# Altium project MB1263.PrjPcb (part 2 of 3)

## Sheet MPU_18x18.SchDoc: MPU_18x18
size A3; DocumentNumber: MB1263; Revision: C-04; SheetNumber: 3; SheetTotal: 11; Project: STM32MP157-EVAL
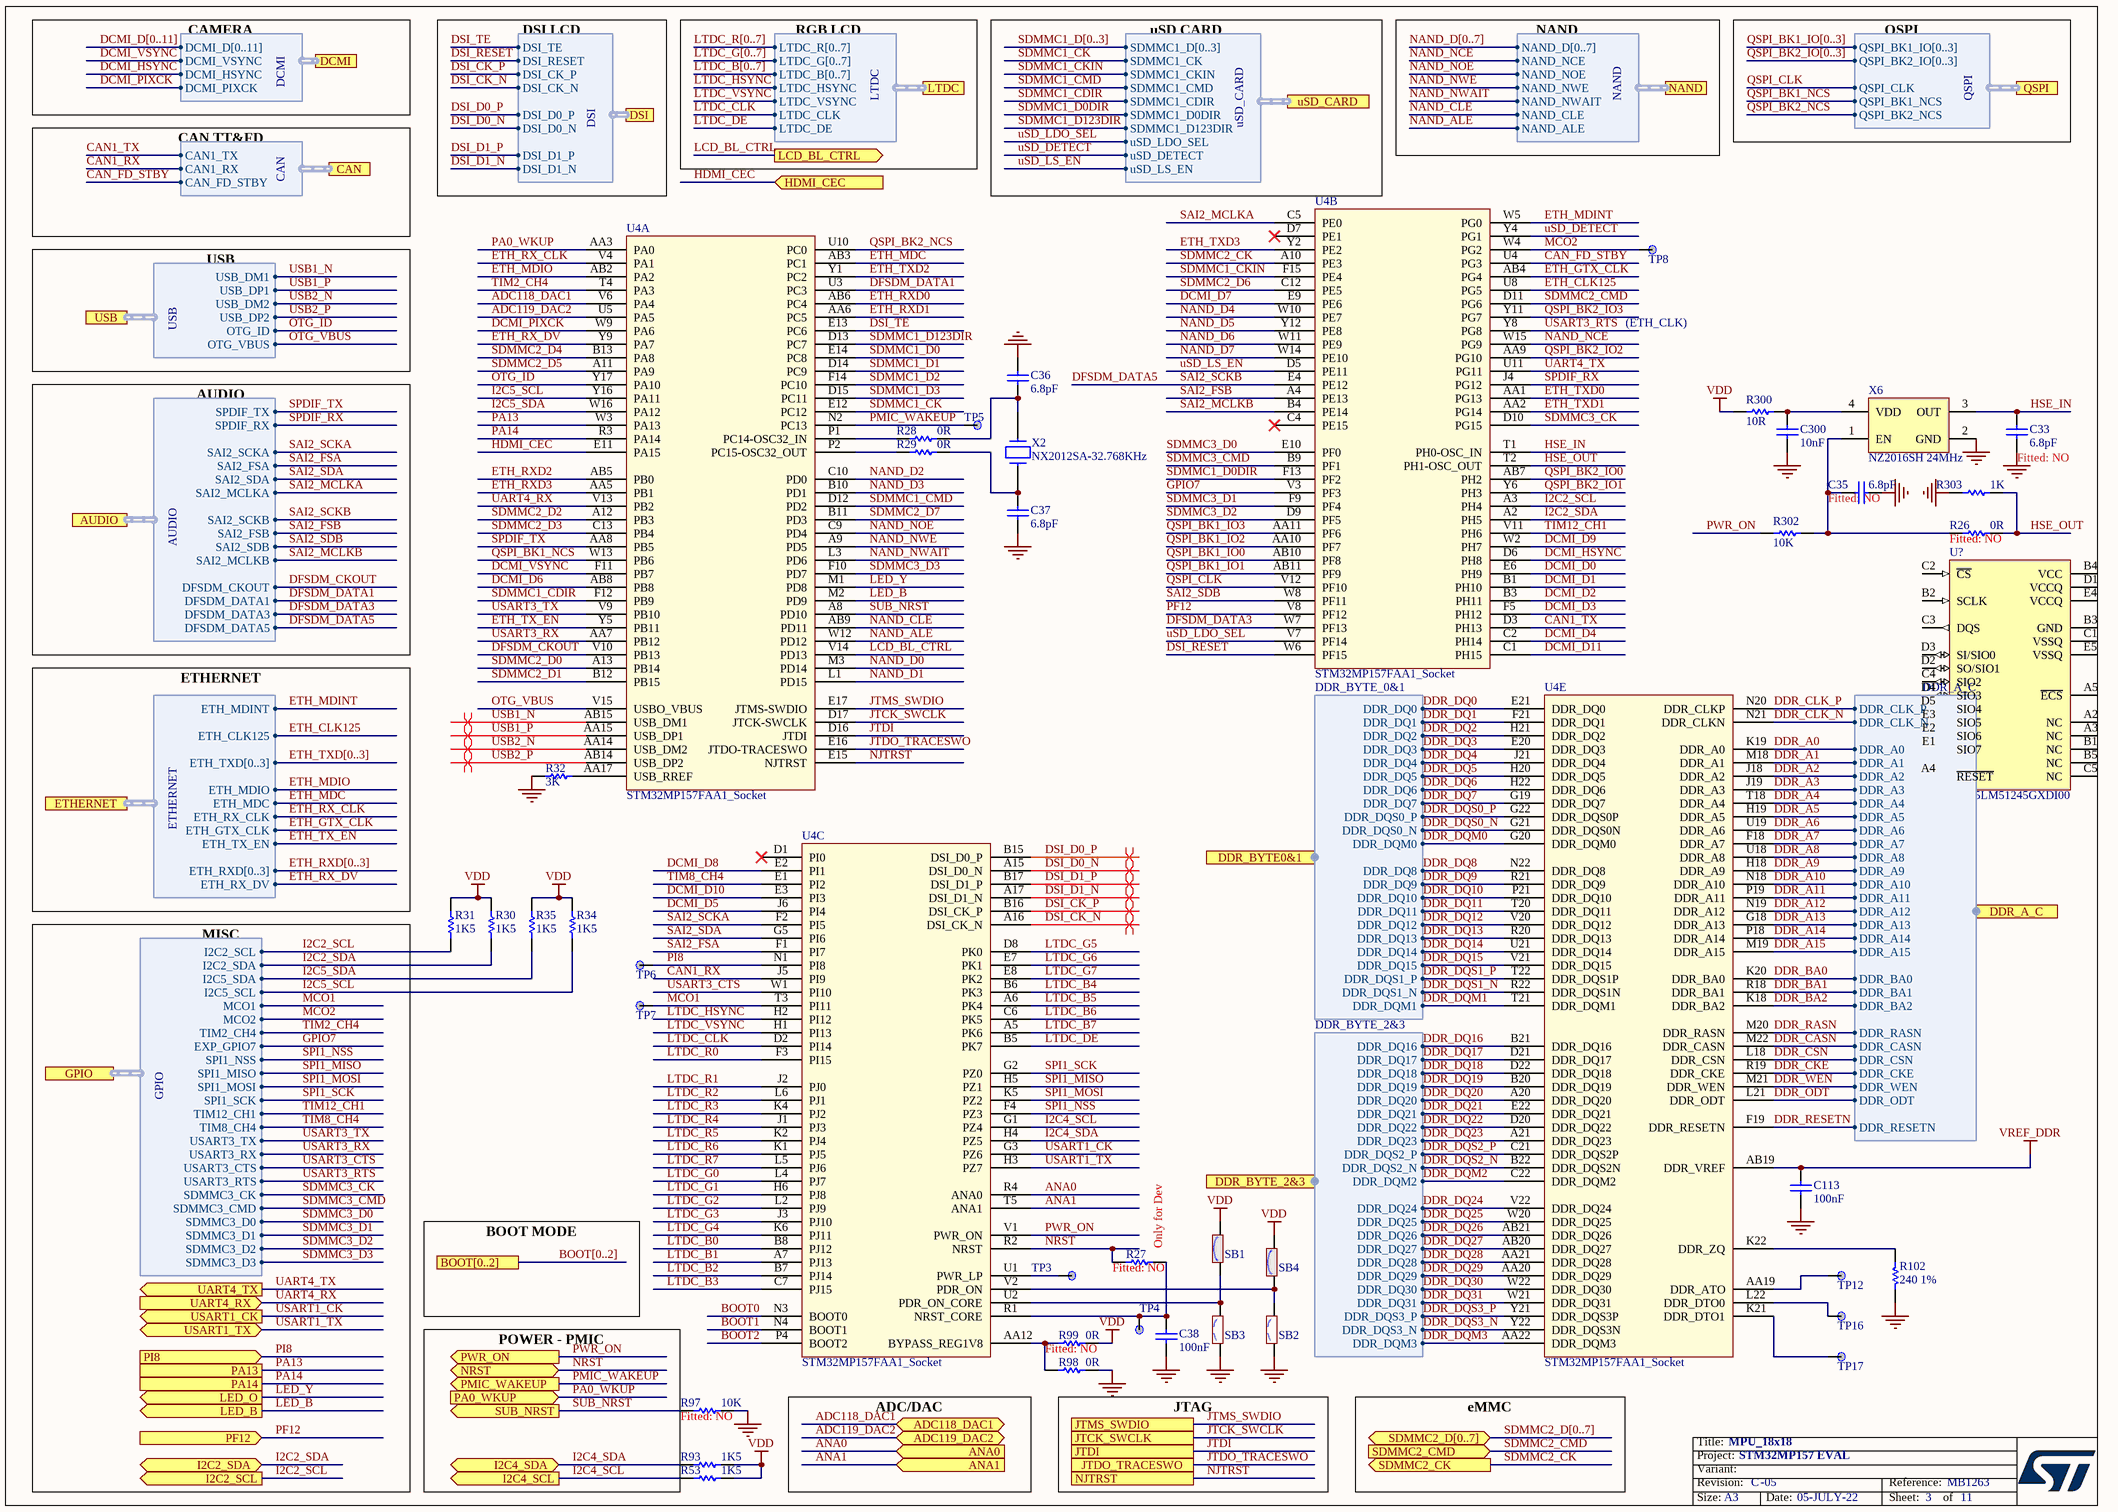
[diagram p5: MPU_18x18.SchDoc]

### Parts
C33  Fitted: NO  [C0402]  (hidden comment: 6.8pF)
C35  Fitted: NO  [C0402]  (hidden comment: 6.8pF)
C36  6.8pF  [C0402]
C37  6.8pF  [C0402]
C38  100nF  [C0402]
C113  100nF  [C0402]
C300  10nF  [C0402]
R26  0R  Fitted: NO  [R0402]
R27  Fitted: NO  [R0402]  (hidden comment: 0R)
R28  0R  [R0402]
R29  0R  [R0402]
R30  1K5  [R0402]
R31  1K5  [R0402]
R32  3K  [R0402]
R34  1K5  [R0402]
R35  1K5  [R0402]
R53  1K5  [R0402]
R93  1K5  [R0402]
R97  10K  Fitted: NO  [R0402]
R98  0R  [R0402]
R99  0R  Fitted: NO  [R0402]
R102  240 1%  [R0402]
R300  value 10R  [R0402]  (hidden comment: Resistor)
R302  10K  [R0402]
R303  1K  [R0402]
SB1  SB_ON  [SOLDER-BRIDGE_R0603-0R]  (value not drawn)
SB2  SB_OFF  [SOLDER-BRIDGE_R0603-0R]  (value not drawn)
SB3  SB_OFF  [SOLDER-BRIDGE_R0603-0R]  (value not drawn)
SB4  SB_ON  [SOLDER-BRIDGE_R0603-0R]  (value not drawn)
TP3  TP  [TP_SMD_1MM]  (value not drawn)  (no BOM)
TP4  TP  [TP_SMD_1MM]  (value not drawn)  (no BOM)
TP5  TP  [TP_SMD_1MM]  (value not drawn)  (no BOM)
TP6  TP  [TP_SMD_1MM]  (value not drawn)  (no BOM)
TP7  TP  [TP_SMD_1MM]  (value not drawn)  (no BOM)
TP8  TP  [TP_SMD_1MM]  (value not drawn)  (no BOM)
TP12  TP 0.6  [TP_SMD_0-6MM]  (value not drawn)  (no BOM)
TP16  TP 0.6  [TP_SMD_0-6MM]  (value not drawn)  (no BOM)
TP17  TP 0.6  [TP_SMD_0-6MM]  (value not drawn)  (no BOM)
U4  STM32MP157FAA1_Socket  [ICC_LFBGA448_18X18_STM32MP157BAA3_P080__SOCKET_IE_CS1627194MF]  (parts A,B,C,E of 5)
U?  value MX25LM51245GXDI00  [ICC_BGA24_5X5-BALL-ARRAY_6X8_P1]  (hidden comment: MX25xx51245GXDx00)
X2  NX2012SA-32.768KHz  [CRY_NX2012SA_2P]
X6  value NZ2016SH 24MHz  [CRY_NZ2016SH_4P]  (hidden comment: OSCILLATOR_4_PINS)

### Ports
ADC118_DAC1 (bidir), ADC119_DAC2 (bidir), ANA0 (in), ANA1 (in), AUDIO (harness AUDIO), BOOT[0..2], CAN (harness CAN), DCMI (harness DCMI), DDR_A_C (harness DDR_A_C), DDR_BYTE0&1 (harness DDR_BYTE_0&1), DDR_BYTE_2&3 (harness DDR_BYTE_2&3), DSI (harness DSI), ETHERNET (harness ETHERNET), GPIO (harness GPIO), HDMI_CEC (in), I2C2_SCL (out), I2C2_SDA (bidir), I2C4_SCL (out), I2C4_SDA (bidir), JTCK_SWCLK, JTDI, JTDO_TRACESWO, JTMS_SWDIO, LCD_BL_CTRL (out), LED_B (out), LED_O (out), LTDC (harness LTDC), NAND (harness NAND), NJTRST, NRST (bidir), PA0_WKUP (in), PA13, PA14, PF12 (in), PI8 (in), PMIC_WAKEUP (out), PWR_ON (out), QSPI (harness QSPI), SDMMC2_CK (out), SDMMC2_CMD (in), SDMMC2_D[0..7] (bidir), SUB_NRST (out), UART4_RX (in), UART4_TX (out), USART1_CK (out), USART1_TX (bidir), USB (harness USB), uSD_CARD (harness uSD_CARD)

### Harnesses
DDR_BYTE_0&1: DDR_DQ0, DDR_DQ1, DDR_DQ2, DDR_DQ3, DDR_DQ4, DDR_DQ5, DDR_DQ6, DDR_DQ7, DDR_DQS0_P, DDR_DQS0_N, DDR_DQM0, DDR_DQ8, DDR_DQ9, DDR_DQ10, DDR_DQ11, DDR_DQ12, DDR_DQ13, DDR_DQ14, DDR_DQ15, DDR_DQS1_P, DDR_DQS1_N, DDR_DQM1
DDR_BYTE_2&3: DDR_DQ16, DDR_DQ17, DDR_DQ18, DDR_DQ19, DDR_DQ20, DDR_DQ21, DDR_DQ22, DDR_DQ23, DDR_DQS2_P, DDR_DQS2_N, DDR_DQM2, DDR_DQ24, DDR_DQ25, DDR_DQ26, DDR_DQ27, DDR_DQ28, DDR_DQ29, DDR_DQ30, DDR_DQ31, DDR_DQS3_P, DDR_DQS3_N, DDR_DQM3
DDR_A_C: DDR_CLK_P, DDR_CLK_N, DDR_A0, DDR_A1, DDR_A2, DDR_A3, DDR_A4, DDR_A5, DDR_A6, DDR_A7, DDR_A8, DDR_A9, DDR_A10, DDR_A11, DDR_A12, DDR_A13, DDR_A14, DDR_A15, DDR_BA0, DDR_BA1, DDR_BA2, DDR_RASN, DDR_CASN, DDR_CSN, DDR_CKE, DDR_WEN, DDR_ODT, DDR_RESETN
GPIO: I2C2_SCL, I2C2_SDA, I2C5_SDA, MCO1, MCO2, TIM2_CH4, EXP_GPIO7, SPI1_NSS, SPI1_MISO, SPI1_MOSI, SPI1_SCK, TIM12_CH1, TIM8_CH4, USART3_TX, USART3_RX, USART3_CTS, USART3_RTS, SDMMC3_CK, SDMMC3_CMD, SDMMC3_D0, SDMMC3_D1, SDMMC3_D2, SDMMC3_D3, I2C5_SCL
ETHERNET: ETH_MDINT, ETH_CLK125, ETH_TXD[0..3], ETH_MDIO, ETH_MDC, ETH_RX_CLK, ETH_GTX_CLK, ETH_TX_EN, ETH_RXD[0..3], ETH_RX_DV
AUDIO: SPDIF_TX, SPDIF_RX, SAI2_SCKA, SAI2_FSA, SAI2_SDA, SAI2_SDB, SAI2_MCLKA, DFSDM_CKOUT, DFSDM_DATA1, DFSDM_DATA3, DFSDM_DATA5, SAI2_SCKB, SAI2_FSB, SAI2_MCLKB
DCMI: DCMI_D[0..11], DCMI_VSYNC, DCMI_HSYNC, DCMI_PIXCK
DSI: DSI_CK_P, DSI_CK_N, DSI_D0_P, DSI_D0_N, DSI_D1_P, DSI_D1_N, DSI_TE, DSI_RESET
LTDC: LTDC_R[0..7], LTDC_G[0..7], LTDC_B[0..7], LTDC_HSYNC, LTDC_VSYNC, LTDC_CLK, LTDC_DE
NAND: NAND_D[0..7], NAND_NCE, NAND_NOE, NAND_NWE, NAND_NWAIT, NAND_CLE, NAND_ALE
USB: USB_DM1, USB_DP1, USB_DM2, USB_DP2, OTG_ID, OTG_VBUS
QSPI: QSPI_BK1_IO[0..3], QSPI_BK2_IO[0..3], QSPI_CLK, QSPI_BK1_NCS, QSPI_BK2_NCS
uSD_CARD: SDMMC1_D[0..3], SDMMC1_CK, SDMMC1_CKIN, SDMMC1_CMD, SDMMC1_CDIR, SDMMC1_D0DIR, SDMMC1_D123DIR, uSD_LDO_SEL, uSD_DETECT, uSD_LS_EN
CAN: CAN1_TX, CAN1_RX, CAN_FD_STBY

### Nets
GND: C33.1 C35.1 C36.2 C37.1 C38.1 C113.1 C300.1 R32.1 R97.2 R98.2 R102.2 R303.2 SB2.1 SB3.1 X6.2(GND)
VDD: R30.2 R31.2 R34.2 R35.2 R53.1 R93.1 R99.2 R300.1 SB1.2 SB4.2
VREF_DDR: C113.2 U4.AB19(DDR_VREF)
ADC118_DAC1: U4.V6(PA4) ; port ADC118_DAC1
ADC119_DAC2: U4.U5(PA5) ; port ADC119_DAC2
ANA0: U4.R4(ANA0) ; port ANA0
ANA1: U4.T5(ANA1) ; port ANA1
BOOT0: U4.N3(BOOT0)
BOOT1: U4.N4(BOOT1)
BOOT2: U4.P4(BOOT2)
CAN1_RX: U4.J5(PI9) ; port CAN.CAN1_RX
CAN1_TX: U4.D3(PH13) ; port CAN.CAN1_TX
CAN_FD_STBY: U4.U4(PG3) ; port CAN.CAN_FD_STBY
DCMI_D0: U4.E6(PH9)
DCMI_D1: U4.B1(PH10)
DCMI_D2: U4.B3(PH11)
DCMI_D3: U4.F5(PH12)
DCMI_D4: U4.C2(PH14)
DCMI_D5: U4.J6(PI4)
DCMI_D6: U4.AB8(PB8)
DCMI_D7: U4.E9(PE6)
DCMI_D8: U4.E2(PI1)
DCMI_D9: U4.W2(PH7)
DCMI_D10: U4.E3(PI3)
DCMI_D11: U4.C1(PH15)
DCMI_HSYNC: U4.D6(PH8) ; port DCMI.DCMI_HSYNC
DCMI_PIXCK: U4.W9(PA6) ; port DCMI.DCMI_PIXCK
DCMI_VSYNC: U4.F11(PB7) ; port DCMI.DCMI_VSYNC
DDR_A0: U4.K19(DDR_A0) ; port DDR_A_C.DDR_A0
DDR_A1: U4.M18(DDR_A1) ; port DDR_A_C.DDR_A1
DDR_A2: U4.J18(DDR_A2) ; port DDR_A_C.DDR_A2
DDR_A3: U4.J19(DDR_A3) ; port DDR_A_C.DDR_A3
DDR_A4: U4.T18(DDR_A4) ; port DDR_A_C.DDR_A4
DDR_A5: U4.H19(DDR_A5) ; port DDR_A_C.DDR_A5
DDR_A6: U4.U19(DDR_A6) ; port DDR_A_C.DDR_A6
DDR_A7: U4.F18(DDR_A7) ; port DDR_A_C.DDR_A7
DDR_A8: U4.U18(DDR_A8) ; port DDR_A_C.DDR_A8
DDR_A9: U4.H18(DDR_A9) ; port DDR_A_C.DDR_A9
DDR_A10: U4.N18(DDR_A10) ; port DDR_A_C.DDR_A10
DDR_A11: U4.P19(DDR_A11) ; port DDR_A_C.DDR_A11
DDR_A12: U4.N19(DDR_A12) ; port DDR_A_C.DDR_A12
DDR_A13: U4.G18(DDR_A13) ; port DDR_A_C.DDR_A13
DDR_A14: U4.P18(DDR_A14) ; port DDR_A_C.DDR_A14
DDR_A15: U4.M19(DDR_A15) ; port DDR_A_C.DDR_A15
DDR_BA0: U4.K20(DDR_BA0) ; port DDR_A_C.DDR_BA0
DDR_BA1: U4.R18(DDR_BA1) ; port DDR_A_C.DDR_BA1
DDR_BA2: U4.K18(DDR_BA2) ; port DDR_A_C.DDR_BA2
DDR_CASN: U4.M22(DDR_CASN) ; port DDR_A_C.DDR_CASN
DDR_CKE: U4.R19(DDR_CKE) ; port DDR_A_C.DDR_CKE
DDR_CLK_N: U4.N21(DDR_CLKN) ; port DDR_A_C.DDR_CLK_N
DDR_CLK_P: U4.N20(DDR_CLKP) ; port DDR_A_C.DDR_CLK_P
DDR_CSN: U4.L18(DDR_CSN) ; port DDR_A_C.DDR_CSN
DDR_DQ0: U4.E21(DDR_DQ0) ; port DDR_BYTE0&1.DDR_DQ0
DDR_DQ1: U4.F21(DDR_DQ1) ; port DDR_BYTE0&1.DDR_DQ1
DDR_DQ2: U4.H21(DDR_DQ2) ; port DDR_BYTE0&1.DDR_DQ2
DDR_DQ3: U4.E20(DDR_DQ3) ; port DDR_BYTE0&1.DDR_DQ3
DDR_DQ4: U4.J21(DDR_DQ4) ; port DDR_BYTE0&1.DDR_DQ4
DDR_DQ5: U4.H20(DDR_DQ5) ; port DDR_BYTE0&1.DDR_DQ5
DDR_DQ6: U4.H22(DDR_DQ6) ; port DDR_BYTE0&1.DDR_DQ6
DDR_DQ7: U4.G19(DDR_DQ7) ; port DDR_BYTE0&1.DDR_DQ7
DDR_DQ8: U4.N22(DDR_DQ8) ; port DDR_BYTE0&1.DDR_DQ8
DDR_DQ9: U4.R21(DDR_DQ9) ; port DDR_BYTE0&1.DDR_DQ9
DDR_DQ10: U4.P21(DDR_DQ10) ; port DDR_BYTE0&1.DDR_DQ10
DDR_DQ11: U4.T20(DDR_DQ11) ; port DDR_BYTE0&1.DDR_DQ11
DDR_DQ12: U4.V20(DDR_DQ12) ; port DDR_BYTE0&1.DDR_DQ12
DDR_DQ13: U4.R20(DDR_DQ13) ; port DDR_BYTE0&1.DDR_DQ13
DDR_DQ14: U4.U21(DDR_DQ14) ; port DDR_BYTE0&1.DDR_DQ14
DDR_DQ15: U4.V21(DDR_DQ15) ; port DDR_BYTE0&1.DDR_DQ15
DDR_DQ16: U4.B21(DDR_DQ16) ; port DDR_BYTE_2&3.DDR_DQ16
DDR_DQ17: U4.D21(DDR_DQ17) ; port DDR_BYTE_2&3.DDR_DQ17
DDR_DQ18: U4.D22(DDR_DQ18) ; port DDR_BYTE_2&3.DDR_DQ18
DDR_DQ19: U4.B20(DDR_DQ19) ; port DDR_BYTE_2&3.DDR_DQ19
DDR_DQ20: U4.A20(DDR_DQ20) ; port DDR_BYTE_2&3.DDR_DQ20
DDR_DQ21: U4.E22(DDR_DQ21) ; port DDR_BYTE_2&3.DDR_DQ21
DDR_DQ22: U4.D20(DDR_DQ22) ; port DDR_BYTE_2&3.DDR_DQ22
DDR_DQ23: U4.A21(DDR_DQ23) ; port DDR_BYTE_2&3.DDR_DQ23
DDR_DQ24: U4.V22(DDR_DQ24) ; port DDR_BYTE_2&3.DDR_DQ24
DDR_DQ25: U4.W20(DDR_DQ25) ; port DDR_BYTE_2&3.DDR_DQ25
DDR_DQ26: U4.AB21(DDR_DQ26) ; port DDR_BYTE_2&3.DDR_DQ26
DDR_DQ27: U4.AB20(DDR_DQ27) ; port DDR_BYTE_2&3.DDR_DQ27
DDR_DQ28: U4.AA21(DDR_DQ28) ; port DDR_BYTE_2&3.DDR_DQ28
DDR_DQ29: U4.AA20(DDR_DQ29) ; port DDR_BYTE_2&3.DDR_DQ29
DDR_DQ30: U4.W22(DDR_DQ30) ; port DDR_BYTE_2&3.DDR_DQ30
DDR_DQ31: U4.W21(DDR_DQ31) ; port DDR_BYTE_2&3.DDR_DQ31
DDR_DQM0: U4.G20(DDR_DQM0) ; port DDR_BYTE0&1.DDR_DQM0
DDR_DQM1: U4.T21(DDR_DQM1) ; port DDR_BYTE0&1.DDR_DQM1
DDR_DQM2: U4.C22(DDR_DQM2) ; port DDR_BYTE_2&3.DDR_DQM2
DDR_DQM3: U4.AA22(DDR_DQM3) ; port DDR_BYTE_2&3.DDR_DQM3
DDR_DQS0_N: U4.G21(DDR_DQS0N) ; port DDR_BYTE0&1.DDR_DQS0_N
DDR_DQS0_P: U4.G22(DDR_DQS0P) ; port DDR_BYTE0&1.DDR_DQS0_P
DDR_DQS1_N: U4.R22(DDR_DQS1N) ; port DDR_BYTE0&1.DDR_DQS1_N
DDR_DQS1_P: U4.T22(DDR_DQS1P) ; port DDR_BYTE0&1.DDR_DQS1_P
DDR_DQS2_N: U4.B22(DDR_DQS2N) ; port DDR_BYTE_2&3.DDR_DQS2_N
DDR_DQS2_P: U4.C21(DDR_DQS2P) ; port DDR_BYTE_2&3.DDR_DQS2_P
DDR_DQS3_N: U4.Y22(DDR_DQS3N) ; port DDR_BYTE_2&3.DDR_DQS3_N
DDR_DQS3_P: U4.Y21(DDR_DQS3P) ; port DDR_BYTE_2&3.DDR_DQS3_P
DDR_ODT: U4.L21(DDR_ODT) ; port DDR_A_C.DDR_ODT
DDR_RASN: U4.M20(DDR_RASN) ; port DDR_A_C.DDR_RASN
DDR_RESETN: U4.F19(DDR_RESETN) ; port DDR_A_C.DDR_RESETN
DDR_WEN: U4.M21(DDR_WEN) ; port DDR_A_C.DDR_WEN
DFSDM_CKOUT: U4.V10(PB13) ; port AUDIO.DFSDM_CKOUT
DFSDM_DATA1: U4.U3(PC3) ; port AUDIO.DFSDM_DATA1
DFSDM_DATA3: U4.W7(PF13) ; port AUDIO.DFSDM_DATA3
DFSDM_DATA5: U4.E4(PE12) ; port AUDIO.DFSDM_DATA5, port AUDIO.SAI2_SCKB  [also labelled SAI2_SCKB]
DSI_CK_N: U4.A16(DSI_CK_N) ; port DSI.DSI_CK_N
DSI_CK_P: U4.B16(DSI_CK_P) ; port DSI.DSI_CK_P
DSI_D0_N: U4.A15(DSI_D0_N) ; port DSI.DSI_D0_N
DSI_D0_P: U4.B15(DSI_D0_P) ; port DSI.DSI_D0_P
DSI_D1_N: U4.A17(DSI_D1_N) ; port DSI.DSI_D1_N
DSI_D1_P: U4.B17(DSI_D1_P) ; port DSI.DSI_D1_P
DSI_RESET: U4.W6(PF15) ; port DSI.DSI_RESET
DSI_TE: U4.E13(PC6) ; port DSI.DSI_TE
ETH_CLK125: U4.U8(PG5) ; port ETHERNET.ETH_CLK125
ETH_GTX_CLK: U4.AB4(PG4) ; port ETHERNET.ETH_GTX_CLK
ETH_MDC: U4.AB3(PC1) ; port ETHERNET.ETH_MDC
ETH_MDINT: U4.W5(PG0) ; port ETHERNET.ETH_MDINT
ETH_MDIO: U4.AB2(PA2) ; port ETHERNET.ETH_MDIO
ETH_RX_CLK: U4.V4(PA1) ; port ETHERNET.ETH_RX_CLK
ETH_RX_DV: U4.Y9(PA7) ; port ETHERNET.ETH_RX_DV
ETH_RXD0: U4.AB6(PC4)
ETH_RXD1: U4.AA6(PC5)
ETH_RXD2: U4.AB5(PB0)
ETH_RXD3: U4.AA5(PB1)
ETH_TX_EN: U4.Y5(PB11) ; port ETHERNET.ETH_TX_EN
ETH_TXD0: U4.AA1(PG13)
ETH_TXD1: U4.AA2(PG14)
ETH_TXD2: U4.Y1(PC2)
ETH_TXD3: U4.Y2(PE2)
GPIO7: U4.V3(PF3) ; port GPIO.EXP_GPIO7
HDMI_CEC: U4.E11(PA15) ; port HDMI_CEC
HSE_IN: C33.2 U4.T1(PH0-OSC_IN) X6.3(OUT)
HSE_OUT: R26.2 R303.1 U4.T2(PH1-OSC_OUT)
I2C2_SCL: R31.1 U4.A3(PH4) ; port I2C2_SCL, port GPIO.I2C2_SCL
I2C2_SDA: R30.1 U4.A2(PH5) ; port I2C2_SDA, port GPIO.I2C2_SDA
I2C4_SCL: R53.2 U4.G1(PZ4) ; port I2C4_SCL
I2C4_SDA: R93.2 U4.H4(PZ5) ; port I2C4_SDA
I2C5_SCL: R34.1 U4.Y16(PA11) ; port GPIO.I2C5_SCL
I2C5_SDA: R35.1 U4.W16(PA12) ; port GPIO.I2C5_SDA
JTCK_SWCLK: U4.D17(JTCK-SWCLK) ; port JTCK_SWCLK
JTDI: U4.D16(JTDI) ; port JTDI
JTDO_TRACESWO: U4.E16(JTDO-TRACESWO) ; port JTDO_TRACESWO
JTMS_SWDIO: U4.E17(JTMS-SWDIO) ; port JTMS_SWDIO
LCD_BL_CTRL: U4.V14(PD13) ; port LCD_BL_CTRL
LED_B: U4.M2(PD9) ; port LED_B
LED_Y: U4.M1(PD8) ; port LED_O
LTDC_B0: U4.B8(PJ12)
LTDC_B1: U4.A7(PJ13)
LTDC_B2: U4.B7(PJ14)
LTDC_B3: U4.C7(PJ15)
LTDC_B4: U4.B6(PK3)
LTDC_B5: U4.A6(PK4)
LTDC_B6: U4.C6(PK5)
LTDC_B7: U4.A5(PK6)
LTDC_CLK: U4.D2(PI14) ; port LTDC.LTDC_CLK
LTDC_DE: U4.B5(PK7) ; port LTDC.LTDC_DE
LTDC_G0: U4.L4(PJ7)
LTDC_G1: U4.H6(PJ8)
LTDC_G2: U4.L2(PJ9)
LTDC_G3: U4.J3(PJ10)
LTDC_G4: U4.K6(PJ11)
LTDC_G5: U4.D8(PK0)
LTDC_G6: U4.E7(PK1)
LTDC_G7: U4.E8(PK2)
LTDC_HSYNC: U4.H2(PI12) ; port LTDC.LTDC_HSYNC
LTDC_R0: U4.F3(PI15)
LTDC_R1: U4.J2(PJ0)
LTDC_R2: U4.L6(PJ1)
LTDC_R3: U4.K4(PJ2)
LTDC_R4: U4.J1(PJ3)
LTDC_R5: U4.K2(PJ4)
LTDC_R6: U4.K1(PJ5)
LTDC_R7: U4.L5(PJ6)
LTDC_VSYNC: U4.H1(PI13) ; port LTDC.LTDC_VSYNC
MCO1: TP7.1 U4.T3(PI11) ; port GPIO.MCO1
MCO2: TP8.1 U4.W4(PG2) ; port GPIO.MCO2
NAND_ALE: U4.W12(PD12) ; port NAND.NAND_ALE
NAND_CLE: U4.AB9(PD11) ; port NAND.NAND_CLE
NAND_D0: U4.M3(PD14)
NAND_D1: U4.L1(PD15)
NAND_D2: U4.C10(PD0)
NAND_D3: U4.B10(PD1)
NAND_D4: U4.W10(PE7)
NAND_D5: U4.Y12(PE8)
NAND_D6: U4.W11(PE9)
NAND_D7: U4.W14(PE10)
NAND_NCE: U4.W15(PG9) ; port NAND.NAND_NCE
NAND_NOE: U4.C9(PD4) ; port NAND.NAND_NOE
NAND_NWAIT: U4.L3(PD6) ; port NAND.NAND_NWAIT
NAND_NWE: U4.A9(PD5) ; port NAND.NAND_NWE
NJTRST: U4.E15(NJTRST) ; port NJTRST
NRST: R27.2 U4.R2(NRST) ; port NRST
OTG_ID: U4.Y17(PA10) ; port USB.OTG_ID
OTG_VBUS: U4.V15(USBO_VBUS) ; port USB.OTG_VBUS
PA0_WKUP: U4.AA3(PA0) ; port PA0_WKUP
PA13: U4.W3(PA13) ; port PA13
PA14: U4.R3(PA14) ; port PA14
PF12: U4.V8(PF12) ; port PF12
PI8: TP6.1 U4.N1(PI8) ; port PI8
PMIC_WAKEUP: TP5.1 U4.N2(PC13) ; port PMIC_WAKEUP
PWR_ON: R302.1 U4.V1(PWR_ON) ; port PWR_ON
QSPI_BK1_IO0: U4.AB10(PF8)
QSPI_BK1_IO1: U4.AB11(PF9)
QSPI_BK1_IO2: U4.AA10(PF7)
QSPI_BK1_IO3: U4.AA11(PF6)
QSPI_BK1_NCS: U4.W13(PB6) ; port QSPI.QSPI_BK1_NCS
QSPI_BK2_IO0: U4.AB7(PH2)
QSPI_BK2_IO1: U4.Y6(PH3)
QSPI_BK2_IO2: U4.AA9(PG10)
QSPI_BK2_IO3: U4.Y11(PG7)
QSPI_BK2_NCS: U4.U10(PC0) ; port QSPI.QSPI_BK2_NCS
QSPI_CLK: U4.V12(PF10) ; port QSPI.QSPI_CLK
SAI2_FSA: U4.F1(PI7) ; port AUDIO.SAI2_FSA
SAI2_FSB: U4.A4(PE13) ; port AUDIO.SAI2_FSB
SAI2_MCLKA: U4.C5(PE0) ; port AUDIO.SAI2_MCLKA
SAI2_MCLKB: U4.B4(PE14) ; port AUDIO.SAI2_MCLKB
SAI2_SCKA: U4.F2(PI5) ; port AUDIO.SAI2_SCKA
SAI2_SDA: U4.G5(PI6) ; port AUDIO.SAI2_SDA
SAI2_SDB: U4.W8(PF11) ; port AUDIO.SAI2_SDB
SDMMC1_CDIR: U4.F12(PB9) ; port uSD_CARD.SDMMC1_CDIR
SDMMC1_CK: U4.E12(PC12) ; port uSD_CARD.SDMMC1_CK
SDMMC1_CKIN: U4.F15(PE4) ; port uSD_CARD.SDMMC1_CKIN
SDMMC1_CMD: U4.D12(PD2) ; port uSD_CARD.SDMMC1_CMD
SDMMC1_D0: U4.E14(PC8)
SDMMC1_D0DIR: U4.F13(PF2) ; port uSD_CARD.SDMMC1_D0DIR
SDMMC1_D1: U4.D14(PC9)
SDMMC1_D2: U4.F14(PC10)
SDMMC1_D3: U4.D15(PC11)
SDMMC1_D123DIR: U4.D13(PC7) ; port uSD_CARD.SDMMC1_D123DIR
SDMMC2_CK: U4.A10(PE3) ; port SDMMC2_CK
SDMMC2_CMD: U4.D11(PG6) ; port SDMMC2_CMD
SDMMC2_D0: U4.A13(PB14)
SDMMC2_D1: U4.B12(PB15)
SDMMC2_D2: U4.A12(PB3)
SDMMC2_D3: U4.C13(PB4)
SDMMC2_D4: U4.B13(PA8)
SDMMC2_D5: U4.A11(PA9)
SDMMC2_D6: U4.C12(PE5)
SDMMC2_D7: U4.B11(PD3)
SDMMC3_CK: U4.D10(PG15) ; port GPIO.SDMMC3_CK
SDMMC3_CMD: U4.B9(PF1) ; port GPIO.SDMMC3_CMD
SDMMC3_D0: U4.E10(PF0) ; port GPIO.SDMMC3_D0
SDMMC3_D1: U4.F9(PF4) ; port GPIO.SDMMC3_D1
SDMMC3_D2: U4.D9(PF5) ; port GPIO.SDMMC3_D2
SDMMC3_D3: U4.F10(PD7) ; port GPIO.SDMMC3_D3
SPDIF_RX: U4.J4(PG12) ; port AUDIO.SPDIF_RX
SPDIF_TX: U4.AA8(PB5) ; port AUDIO.SPDIF_TX
SPI1_MISO: U4.H5(PZ1) ; port GPIO.SPI1_MISO
SPI1_MOSI: U4.K5(PZ2) ; port GPIO.SPI1_MOSI
SPI1_NSS: U4.F4(PZ3) ; port GPIO.SPI1_NSS
SPI1_SCK: U4.G2(PZ0) ; port GPIO.SPI1_SCK
SUB_NRST: R97.1 U4.A8(PD10) ; port SUB_NRST
TIM2_CH4: U4.T4(PA3) ; port GPIO.TIM2_CH4
TIM8_CH4: U4.E1(PI2) ; port GPIO.TIM8_CH4
TIM12_CH1: U4.V11(PH6) ; port GPIO.TIM12_CH1
UART4_RX: U4.V13(PB2) ; port UART4_RX
UART4_TX: U4.U11(PG11) ; port UART4_TX
USART1_CK: U4.G3(PZ6) ; port USART1_CK
USART1_TX: U4.H3(PZ7) ; port USART1_TX
USART3_CTS: U4.W1(PI10) ; port GPIO.USART3_CTS
USART3_RTS: U4.Y8(PG8) ; port GPIO.USART3_RTS
USART3_RX: U4.AA7(PB12) ; port GPIO.USART3_RX
USART3_TX: U4.V9(PB10) ; port GPIO.USART3_TX
USB1_N: U4.AB15(USB_DM1) ; port USB.USB_DM1
USB1_P: U4.AA15(USB_DP1) ; port USB.USB_DP1
USB2_N: U4.AA14(USB_DM2) ; port USB.USB_DM2
USB2_P: U4.AB14(USB_DP2) ; port USB.USB_DP2
uSD_DETECT: U4.Y4(PG1) ; port uSD_CARD.uSD_DETECT
uSD_LDO_SEL: U4.V7(PF14) ; port uSD_CARD.uSD_LDO_SEL
uSD_LS_EN: U4.D5(PE11) ; port uSD_CARD.uSD_LS_EN
NetC35_2: C35.2 R26.1 R302.2 X6.1(EN)
NetC36_1: C36.1 R28.2 X2.1
NetC37_2: C37.2 R29.2 X2.2
NetC38_2: C38.2 R27.1 TP4.1 U4.R1(NRST_CORE)
NetC300_2: C300.2 R300.2 X6.4(VDD)
NetR28_1: R28.1 U4.P1(PC14-OSC32_IN)
NetR29_1: R29.1 U4.P2(PC15-OSC32_OUT)
NetR32_2: R32.2 U4.AA17(USB_RREF)
NetR98_1: R98.1 R99.1 U4.AA12(BYPASS_REG1V8)
NetR102_1: R102.1 U4.K22(DDR_ZQ)
NetSB1_1: SB1.1 SB3.2 U4.U2(PDR_ON_CORE)
NetSB2_2: SB2.2 SB4.1 U4.V2(PDR_ON)
NetTP3_1: TP3.1 U4.U1(PWR_LP)
NetTP12_1: TP12.1 U4.AA19(DDR_ATO)
NetTP16_1: TP16.1 U4.L22(DDR_DTO0)
NetTP17_1: TP17.1 U4.K21(DDR_DTO1)

Not connected (* = marked no-connect by the designer): U4 C4(PE15)* D1(PI0)* D7(PE1)*; U? A2(NC) A3(NC) A4(~{RESET}) A5(~{ECS}) B1(NC) B2(SCLK) B3(GND) B4(VCC) B5(NC) C1(VSSQ) C2(~{CS}) C3(DQS) C4(SIO2) C5(NC) D1(VCCQ) D2(SO/SIO1) D3(SI/SIO0) D4(SIO3) D5(SIO4) E1(SIO7) E2(SIO6) E3(SIO5) E4(VCCQ) E5(VSSQ)

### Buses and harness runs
bus BOOT[0..2] = port BOOT[0..2]
bus DCMI_D[0..11]
bus ETH_RXD[0..3]
bus ETH_TXD[0..3]
bus LTDC_B[0..7]
bus LTDC_G[0..7]
bus LTDC_R[0..7]
bus NAND_D[0..7]
bus QSPI_BK1_IO[0..3]
bus QSPI_BK2_IO[0..3]
bus SDMMC1_D[0..3]
bus SDMMC2_D[0..7] = port SDMMC2_D[0..7]

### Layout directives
differential pair: DSI_CK_N, DSI_CK_P, DSI_D0_N, DSI_D0_P, DSI_D1_N, DSI_D1_P, USB1_N, USB1_P, USB2_N, USB2_P

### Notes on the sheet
- CAMERA
- RGB LCD
- NAND
- QSPI
- CAN TT&FD
- DSI LCD
- (near U4) uSD CARD
- USB
- (ETH_CLK)
- AUDIO
- (near R31) ETHERNET
- (near R27) Only for Dev
- BOOT MODE
- (near R31) MISC
- POWER - PMIC
- ADC/DAC
- (near R98) JTAG
- eMMC

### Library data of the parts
C33 C35 = Cap_6.8pF_NPO_0402: Capacitor, MLCC, 6.8pF, 50V, NPO, +-0.25pF, 0402, T=0.5mm; Manuf_Part_1: CC0402CRNPO9BN6R8; Manuf_1: YAGEO; Ordered_By: Subcon
C36 C37 = Cap_6.8pF_NPO_0402: Capacitor, MLCC, 6.8pF, 50V, NPO, +-0.25pF, 0402, T=0.5mm; Manuf_Part_1: CC0402CRNPO9BN6R8; Manuf_1: YAGEO; Fitted: Yes; Ordered_By: Subcon
C38 C113 = Cap_100nF_X7R_10%_0402: Capacitor,100nF,16V,X7R,10%,0402,YAGEO; Manuf_Part_1: CC0402KRX7R7BB104; Fitted: YES; Ordered_By: Subcon
C300 = Cap_10nF_X7R_10%_0402: Capacitor,10nF,16V,X7R,10%,0402,YAGEO; Manuf_Part_1: CC0402KRX7R7BB103; Fitted: YES; Ordered_By: Subcon
R26 R27 R99 = Res_0_5%_0402: Resistor,0R,0402,5%,YAGEO; Manuf_Part_1: RC0402JR-070RL; Order_Code: 2363467; Ordered_By: Subcon
R28 R29 R98 = Res_0_5%_0402: Resistor,0R,0402,5%,YAGEO; Manuf_Part_1: RC0402JR-070RL; Order_Code: 2363467; Fitted: YES; Ordered_By: Subcon
R30 R31 R34 R35 R53 R93 = Res_1K5_1%_0402: Resistor,1K5,0402,1%,YAGEO; Manuf_Part_1: RC0402FR-071K5L; Fitted: YES; Ordered_By: Subcon
R32 = Res_3K_1%_0402: Resistor,3K,0402,1%,YAGEO; Manuf_Part_1: RC0402FR-073KL; Order_Code: 1458777; Fitted: YES; Ordered_By: Subcon
R97 = Res_10K_1%_0402: Resistor,10K,0402,1%,YAGEO; Manuf_Part_1: RC0402FR-0710KL; Ordered_By: Subcon; Order_Code: 9239359RL
R102 = Res_240_1%_0402: Resistor,240R,0402,1%,YAGEO; Manuf_Part_1: RC0402FR-07240RL; Value: 240; Fitted: YES; Ordered_By: Subcon
R300 = Res_10R_1%_0402: Resistor,10R,0402,1%,1/16W; Manuf_Part_1: RC0402FR-0710RL; Manuf_1: YAGEO; Ordered_By: Subcon; Fitted: YES
R302 = Res_10K_1%_0402: Resistor,10K,0402,1%,YAGEO; Manuf_Part_1: RC0402FR-0710KL; Fitted: YES; Ordered_By: Subcon; Order_Code: 9239359RL
R303 = Res_1K_1%_0402: Resistor,1K,0402,1%,YAGEO; Manuf_Part_1: RC0402FR-071KL; Fitted: YES; Ordered_By: Subcon
SB1 SB4 = SB_ON: Solder Bridge ON; Fitted: YES; Ordered_by: Subcon
SB2 SB3 = SB_OFF: Solder Bridge OFF; Fitted: NO; Ordered_By: Subcon; Solder: NO
TP3-TP8 = TP 1mm: Test Point; Fitted: YES
TP12 TP16 TP17 = TP 0.6mm: Test Point; Fitted: YES
U4 = STM32MP157FAA1_Socket: MPU LFBGA18x18 with crypto-Increased Frequency; Manuf_1: ST; ECCN_US/EU: 5A002A4/5A002A4; Fitted: YES; Ordered_By: Subcon
U? = MCD-00246: Memory,Octo-SPI-NOR,512Mb,2048x16,133MHz,3V,DTR,BGA24, CMOS MXSMIO; Part_Type: IC; Part_Preference: Recommended; Manufacturer: MACRONIX; Component_Country_Of_Origin: Unknown; ShowFields: YES; ID: 2623
X2 = XTAL_32K_NX2012SA_527: Crystal 32.768kHz, 6pF, +/-20ppm@25°C; -0.04ppm/°C² ; ESRmax :70Kohm; Manuf_1: NDK; Manuf_Part_1: NX2012SA 32.768kHz EXS00A-MU00527; Ordered_By: Subcon; Fitted: YES
X6 = OSCILLATOR_4_PINS: Oscillator 24Mhz, +-50ppm, Vcc:3.3V typ (1.62V min), square wave: [0.1Vcc;0.9Vcc], Enable pin; Part_Type: Crystal_Osc; Manuf_Part_1: NZ2016SH 24MHz END4869F; Manuf_1: NDK; Ordered_By: Subcon; Fitted: YES

## Sheet SD3 card.SchDoc: MICRO SD 3.0 Card
size A4; DocumentNumber: MB1263; Revision: C-04; SheetNumber: 7; SheetTotal: 11; Project: STM32MP15-EVAL
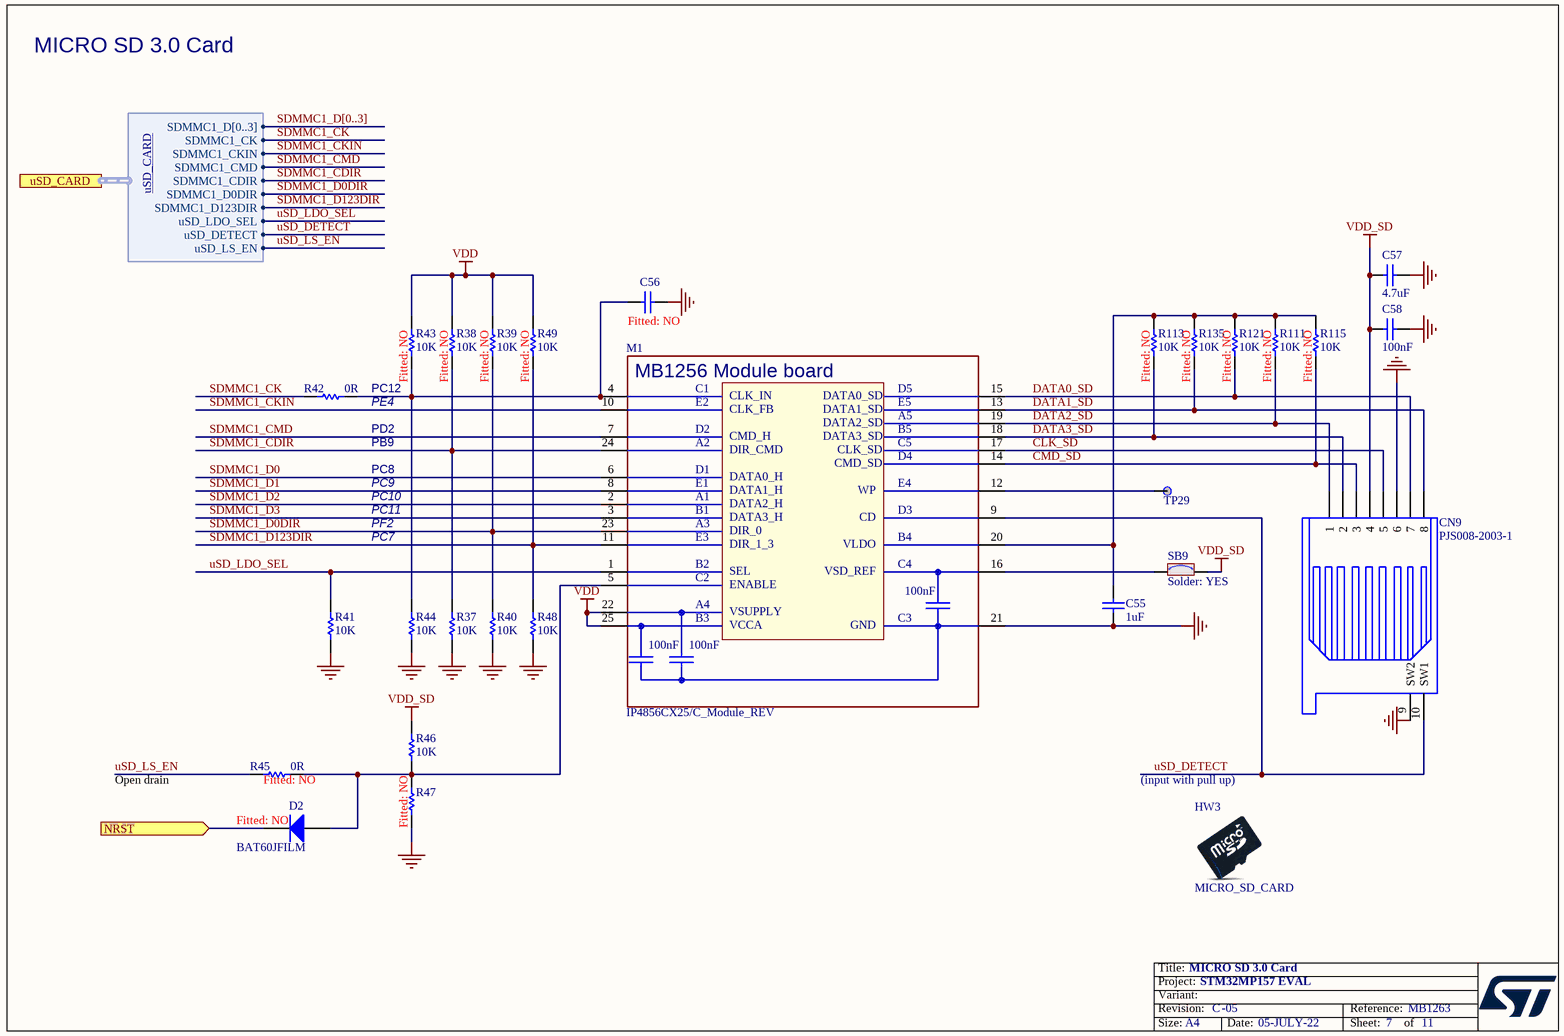
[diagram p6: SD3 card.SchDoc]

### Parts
C55  1uF  [C0603]
C56  Fitted: NO  [C0402]  (hidden comment: 100pF)
C57  4.7uF  [C0603]
C58  100nF  [C0402]
CN9  PJS008-2003-1  [CON_MICROSD_YAMAICHI_PJS008-2003-1]
D2  BAT60JFILM  Fitted: NO  [DIO_SOD323]
HW3  Micro_SD_card  (mechanical)
M1  IP4856CX25/C_Module_REV  [MOD_SD-CARD_8X8_MB1256]
R37  10K  [R0402]
R38  10K  Fitted: NO  [R0402]
R39  10K  Fitted: NO  [R0402]
R40  10K  [R0402]
R41  10K  [R0402]
R42  0R  [R0402]
R43  10K  Fitted: NO  [R0402]
R44  10K  [R0402]
R45  0R  Fitted: NO  [R0402]
R46  10K  [R0402]
R47  Fitted: NO  [R0402]  (hidden comment: 10K)
R48  10K  [R0402]
R49  10K  Fitted: NO  [R0402]
R111  10K  Fitted: NO  [R0402]
R113  10K  Fitted: NO  [R0402]
R115  10K  Fitted: NO  [R0402]
R121  10K  Fitted: NO  [R0402]
R135  10K  Fitted: NO  [R0402]
SB9  Solder: YES  [SOLDER-BRIDGE_R0603-0R]  (hidden comment: SB_ON)
TP29  TP  [TP_SMD_1MM]  (value not drawn)  (no BOM)

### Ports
NRST (in), uSD_CARD (harness uSD_CARD)

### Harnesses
uSD_CARD: SDMMC1_D[0..3], SDMMC1_CK, SDMMC1_CKIN, SDMMC1_CMD, SDMMC1_CDIR, SDMMC1_D0DIR, SDMMC1_D123DIR, uSD_LDO_SEL, uSD_DETECT, uSD_LS_EN

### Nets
GND: C55.1 C56.2 C57.2 C58.1 CN9.6 CN9.9(SW2) M1.21(WP) R37.1 R40.1 R41.1 R44.1 R47.1 R48.1
VDD: M1.22(CD) M1.25(GND) R38.2 R39.2 R43.2 R49.2
VDD_SD: C57.1 C58.2 CN9.4 R46.2 SB9.2
CLK_SD: CN9.5 M1.17(DATA2_SD)
CMD_SD: CN9.3 M1.14(VCCA) R115.1
DATA0_SD: CN9.7 M1.15(DATA0_SD) R121.1
DATA1_SD: CN9.8 M1.13(VSUPPLY) R135.1
DATA2_SD: CN9.1 M1.19(CLK_SD) R111.1
DATA3_SD: CN9.2 M1.18(DATA3_SD) R113.1
NRST: D2.2(K) ; port NRST
SDMMC1_CDIR: M1.24(VSD_REF) R37.2 R38.1 ; port uSD_CARD.SDMMC1_CDIR
SDMMC1_CK: R42.1 ; port uSD_CARD.SDMMC1_CK
SDMMC1_CKIN: M1.10(DIR_1_3) ; port uSD_CARD.SDMMC1_CKIN
SDMMC1_CMD: M1.7(DATA2_H) ; port uSD_CARD.SDMMC1_CMD
SDMMC1_D0: M1.6(DATA1_H)
SDMMC1_D0DIR: M1.23(VLDO) R39.1 R40.2 ; port uSD_CARD.SDMMC1_D0DIR
SDMMC1_D1: M1.8(DATA3_H)
SDMMC1_D2: M1.2(CLK_FB)
SDMMC1_D3: M1.3(CMD_H)
SDMMC1_D123DIR: M1.11(SEL) R48.2 R49.1 ; port uSD_CARD.SDMMC1_D123DIR
uSD_DETECT: CN9.10(SW1) M1.9(DIR_0) ; port uSD_CARD.uSD_DETECT
uSD_LDO_SEL: M1.1(CLK_IN) R41.2 ; port uSD_CARD.uSD_LDO_SEL
uSD_LS_EN: R45.1 ; port uSD_CARD.uSD_LS_EN
NetC55_2: C55.2 M1.20(CMD_SD) R111.2 R113.2 R115.2 R121.2 R135.2
NetC56_1: C56.1 M1.4(DIR_CMD) R42.2 R43.1 R44.2
NetD2_1: D2.1(A) M1.5(DATA0_H) R45.2 R46.1 R47.2
NetM1_12: M1.12(ENABLE) TP29.1
NetM1_16: M1.16(DATA1_SD) SB9.1

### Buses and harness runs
bus SDMMC1_D[0..3]

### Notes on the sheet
- MICRO SD 3.0 Card
- (near R42) PE4
- (near R42) PB9
- (near R42) PD2
- PC12
- PC8
- PC9
- PC10
- PC11
- PF2
- PC7
- Open drain
- (near HW3) (input with pull up)

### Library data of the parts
C55 = Cap_1uF_X5R_10%_0603: Capacitor,1uF,16V,X5R,10%,0603,YAGEO; Manuf_Part_1: CC0603KRX5R7BB105; Fitted: YES; Ordered_By: Subcon
C56 = Cap_100pF_NPO_5%_0402: Capacitor,100pF,50V,NPO,5%,0402,YAGEO; Order_Code: CC0402JRNPO9BN101; Ordered_By: Subcon
C57 = Cap_4.7uF_X5R_20%_0603_16V_MURATA: Capacitor MLCC 4,7uF 20% 16V 3uF@5V ESR=6mohm@100kHz  Z=20mohm@2MHz X5R 0603; Manuf_Part_1: GRM188R61C475MAAJ; Manuf_1: MURATA; Fitted: YES; Ordered_By: Subcon
C58 = Cap_100nF_X7R_10%_0402: as C38 on sheet MPU_18x18
CN9 = microSD-PJS008-2003: Memory Card Connectors MicroSD Card Conn Revrs Mnt Push-Push; Manuf_1: YAMAICHI; Ordered_By: Subcon; Fitted: YES
D2 = BAT60JFILM: Manuf_1: STM; Ordered_By: Subcon; ECCN_US/EU: EAR99/NEC; Ref St: 9151097
HW3 = Micro_SD_card: MICRO_SD_CARD min 8GB class10; Manuf_1: Sandisk; Ordered_By: Subcon; Fitted: YES
M1 = IP4856CX25/C_Module_REV: SDcard3.0 dual voltage level  translator; Manuf_1: STM; Manuf_Part_1: MB1256; ECCN_US/EU: EAR99; Fitted: YES; Ordered_By: Subcon; Value: MB1256
R37 R40 R41 R44 R46 R48 = Res_10K_1%_0402: Resistor,10K,0402,1%,YAGEO; Manuf_Part_1: RC0402FR-0710KL; Order_Code: 9239359RL; Fitted: YES; Ordered_By: Subcon
R38 R39 R43 R47 R49 R111 R113 R115 R121 R135 = Res_10K_1%_0402: Resistor,10K,0402,1%,YAGEO; Manuf_Part_1: RC0402FR-0710KL; Order_Code: 9239359RL; Ordered_By: Subcon
R42 = Res_0_5%_0402: as R28 on sheet MPU_18x18
R45 = Res_0_5%_0402: as R26 on sheet MPU_18x18
SB9 = SB_ON: Solder Bridge ON; Ordered_by: Subcon
TP29 = TP 1mm: Test Point; Fitted: YES

## Sheet Peripherals.SchDoc: Peripherals
size A4; Date: 01-DEC-2013; CompanyName: STMicroelectronics; Organization: Microcontrollers Division; Address1: 12, Rue Jules HOROWITZ; Address2: 38019 Grenoble; Address3: FRANCE; DocumentNumber: MB1263; Revision: C-04; SheetNumber: 11; SheetTotal: 11; Project: STM32MP157-EVAL
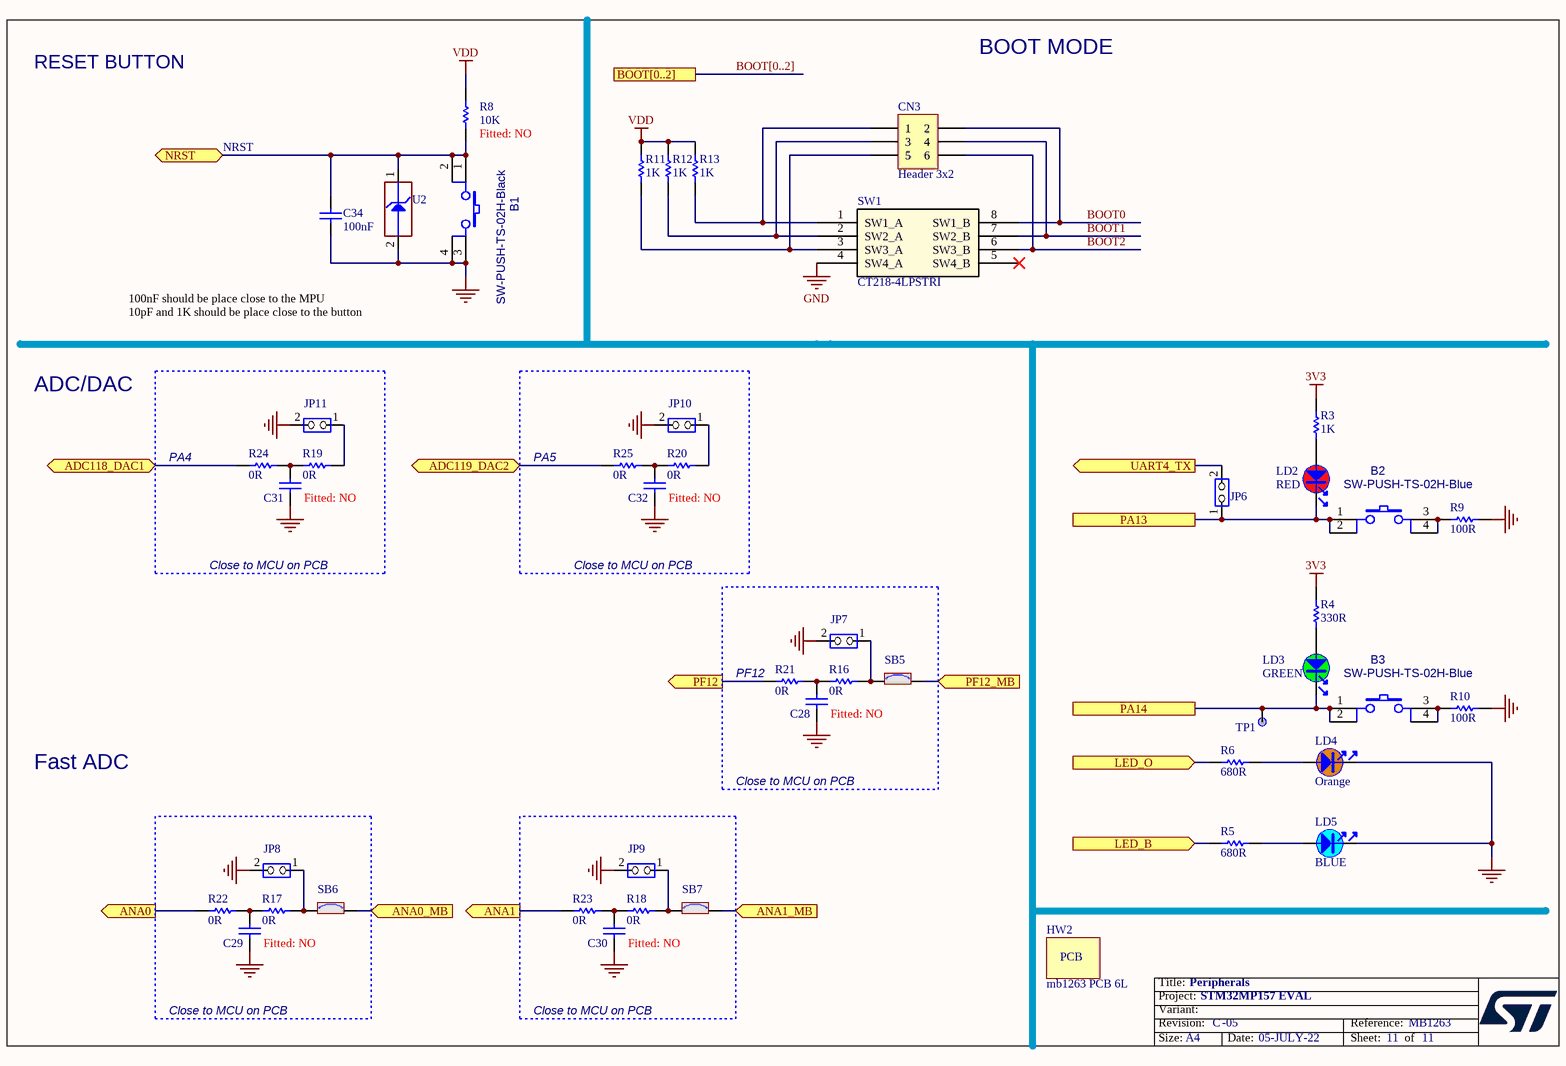
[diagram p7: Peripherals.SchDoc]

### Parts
B1  SW-PUSH-TS-02H-Black  [SWI_JIUBABA_C-TS-02H-2-5-K-V-T_R_BLACK]
B2  SW-PUSH-TS-02H-Blue  [SWI_JIUBABA_C-TS-02H-2-5-B-V-T_R_BLUE]
B3  SW-PUSH-TS-02H-Blue  [SWI_JIUBABA_C-TS-02H-2-5-B-V-T_R_BLUE]
C28  Fitted: NO  [C0402]  (hidden comment: 100nF)
C29  Fitted: NO  [C0402]  (hidden comment: 100nF)
C30  Fitted: NO  [C0402]  (hidden comment: 100nF)
C31  Fitted: NO  [C0402]  (hidden comment: 100nF)
C32  Fitted: NO  [C0402]  (hidden comment: 100nF)
C34  100nF  [C0402]
CN3  Header 3x2  [CON_SAMTEC_TSW-103-07-X-D]
HW2  mb1263 PCB 6L  (mechanical)
JP6  Jumper_2.54mm  [CON_SAMTEC_TSW-102-07-G-S]  (value not drawn)
JP7  Jumper_2.54mm  [CON_SAMTEC_TSW-102-07-G-S]  (value not drawn)
JP8  Jumper_2.54mm  [CON_SAMTEC_TSW-102-07-G-S]  (value not drawn)
JP9  Jumper_2.54mm  [CON_SAMTEC_TSW-102-07-G-S]  (value not drawn)
JP10  Jumper_2.54mm  [CON_SAMTEC_TSW-102-07-G-S]  (value not drawn)
JP11  Jumper_2.54mm  [CON_SAMTEC_TSW-102-07-G-S]  (value not drawn)
LD2  value RED  [LED_0603_RED]  (hidden comment: LED_red)
LD3  value GREEN  [LED_0603_GREEN]  (hidden comment: LED_green)
LD4  value Orange  [LED_0603_ORANGE_H0P4]  (hidden comment: LED_orange)
LD5  value BLUE  [LED_0603_SMD-B_BLUE_H0P4]  (hidden comment: LED_blue)
R3  1K  [R0402]
R4  330R  [R0402]
R5  value 680R  [R0402]  (hidden comment: Resistor)
R6  value 680R  [R0402]  (hidden comment: Resistor)
R8  10K  Fitted: NO  [R0402]
R9  100R  [R0402]
R10  100R  [R0402]
R11  1K  [R0402]
R12  1K  [R0402]
R13  1K  [R0402]
R16  0R  [R0402]
R17  0R  [R0402]
R18  0R  [R0402]
R19  0R  [R0402]
R20  0R  [R0402]
R21  0R  [R0402]
R22  0R  [R0402]
R23  0R  [R0402]
R24  0R  [R0402]
R25  0R  [R0402]
SB5  SB_ON  [SOLDER-BRIDGE_R0603-0R]  (value not drawn)
SB6  SB_ON  [SOLDER-BRIDGE_R0603-0R]  (value not drawn)
SB7  SB_ON  [SOLDER-BRIDGE_R0603-0R]  (value not drawn)
SW1  CT218-4LPSTRI  [SWI_CTS_CTS218-4LP]
TP1  TP  [TP_SMD_1MM]  (value not drawn)  (no BOM)
U2  ESDALC6V1-1U2  [ESD_ST0201]  (value not drawn)

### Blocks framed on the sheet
Close to MCU on PCB: C29 JP8 R17 R22 SB6
Close to MCU on PCB: C30 JP9 R18 R23 SB7

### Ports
ADC118_DAC1 (bidir), ADC119_DAC2 (bidir), ANA0 (out), ANA0_MB (in), ANA1 (out), ANA1_MB (in), BOOT[0..2], LED_B (in), LED_O (in), NRST (bidir), PA13, PA14, PF12 (out), PF12_MB (in), UART4_TX (out)

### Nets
3V3: R3.1 R4.2
GND: B1.3 B1.4 C28.1 C29.1 C30.1 C31.1 C32.1 C34.1 JP7.2(NO) JP8.2(NO) JP9.2(NO) JP10.2(NO) JP11.2(NO) LD4.2 LD5.2 R9.2 R10.2 SW1.4(SW4_A) U2.2(GND)
VDD: R8.2 R11.1 R12.1 R13.1
ADC118_DAC1: R24.1 ; port ADC118_DAC1
ADC119_DAC2: R25.1 ; port ADC119_DAC2
ANA0: R22.1 ; port ANA0
ANA0_MB: SB6.2 ; port ANA0_MB
ANA1: R23.1 ; port ANA1
ANA1_MB: SB7.2 ; port ANA1_MB
BOOT0: CN3.2 SW1.8(SW1_B)
BOOT1: CN3.4 SW1.7(SW2_B)
BOOT2: CN3.6 SW1.6(SW3_B)
LED_B: R5.1 ; port LED_B
LED_Y: R6.1 ; port LED_O
NRST: B1.1 B1.2 C34.2 R8.1 U2.1(IO1) ; port NRST
PA13: B2.1 B2.2 JP6.1(COMMON) LD2.2 ; port PA13
PA14: B3.1 B3.2 LD3.2 TP1.1 ; port PA14
PF12: R21.1 ; port PF12
PF12_MB: SB5.2 ; port PF12_MB
UART4_TX: JP6.2(NO) ; port UART4_TX
NetB2_3: B2.3 B2.4 R9.1
NetB3_3: B3.3 B3.4 R10.1
NetC28_2: C28.2 R16.1 R21.2
NetC29_2: C29.2 R17.1 R22.2
NetC30_2: C30.2 R18.1 R23.2
NetC31_2: C31.2 R19.1 R24.2
NetC32_2: C32.2 R20.1 R25.2
NetCN3_1: CN3.1 R13.2 SW1.1(SW1_A)
NetCN3_3: CN3.3 R12.2 SW1.2(SW2_A)
NetCN3_5: CN3.5 R11.2 SW1.3(SW3_A)
NetJP7_1: JP7.1(COMMON) R16.2 SB5.1
NetJP8_1: JP8.1(COMMON) R17.2 SB6.1
NetJP9_1: JP9.1(COMMON) R18.2 SB7.1
NetJP10_1: JP10.1(COMMON) R20.2
NetJP11_1: JP11.1(COMMON) R19.2
NetLD2_1: LD2.1 R3.2
NetLD3_1: LD3.1 R4.1
NetLD4_1: LD4.1 R6.2
NetLD5_1: LD5.1 R5.2

Not connected (* = marked no-connect by the designer): SW1 5(SW4_B)*

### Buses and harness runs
bus BOOT[0..2] = port BOOT[0..2]

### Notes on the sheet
- BOOT MODE
- RESET BUTTON
- NRST
- 100nF should be place close to the MPU
  10pF and 1K should be place close to the button
- ADC/DAC
- PA4
- PA5
- Close to MCU on PCB
- (near R21) PF12
- Fast ADC

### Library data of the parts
B1 = SW-PUSH-TS-02H-Black: TS-02H SMD Light Touch Switch black; Manuf_1: Jiubaba; Manuf_Part_1: C-TS-02H-2.5-K-V-T/R BLACK; Fitted: YES; Ordered_By: Subcon
B2 B3 = SW-PUSH-TS-02H-Blue: TS-02H SMD Light Touch Switch blue; Manuf_1: Jiubaba; Manuf_Part_1: C-TS-02H-2.5-K-V-T/R BLUE; Ordered_By: Subcon; Fitted: YES
C28-C32 = Cap_100nF_X7R_10%_0402: Capacitor,100nF,16V,X7R,10%,0402,YAGEO; Manuf_Part_1: CC0402KRX7R7BB104; Ordered_By: Subcon
C34 = Cap_100nF_X7R_10%_0402: as C38 on sheet MPU_18x18
CN3 = Header 3x2: Header, 3x2, 2,54mm, VR, TH, Height 5.84mm/2.54mm; Manuf_Part_1: TSW-103-07-x-D; Manuf_1: SAMTEC; Fitted: YES; Ordered_By: Subcon
HW2 = PCB_mb1263: Fitted: YES; Ordered_By: Subcon
JP6-JP11 = TSW-102-07-x-S: Connector jumper 1 position; Manuf_1: SAMTEC; Manuf_Part_2: 4711955140470; Manuf_2: KONTEC; Order_Code: 423-2841; Fitted: YES; Ordered_By: Subcon
LD2 = MCD-02899: LED, Red, VF : Min=1.75V , Max=2.35V, 25mA, 0603; Part_Type: Display; Part_Preference: Recommended; Manufacturer: EVERLIGHT; Manufacturer_Part_Number: 19-213/R6C-AP1Q2B/5T; Full_Alternate_Internal_Part_Number: MCD-00049; Component_Country_Of_Origin: China; ShowFields: YES; ID: 5015
LD3 = MCD-02900: LED, Green, 2V, 25mA, 0603, SMD; Part_Type: Display; Part_Preference: Recommended; Manufacturer: EVERLIGHT; Manufacturer_Part_Number: 19-213SYGC/S530-E2/5T; Full_Alternate_Internal_Part_Number: MCD-00320; Partial_Alternate_Internal_Part_Number: MCD-00050; Component_Country_Of_Origin: China; ShowFields: YES; ID: 5016
LD4 = MCD-02785: LED, Orange, VF: Min=1.7V, Max=2.2V, 25mA, 0603; Part_Type: Display; Part_Preference: Recommended; Manufacturer: EVERLIGHT; Manufacturer_Part_Number: 19-217/S2C-AM2N2VY/6T; Full_Alternate_Internal_Part_Number: MCD-00321; Component_Country_Of_Origin: China; ShowFields: YES; ID: 4897
LD5 = MCD-02786: LED, Blue, VF: Min=2.5V, Max=3.1V, 10mA, 0603; Part_Type: Display; Part_Preference: Recommended; Manufacturer: EVERLIGHT; Manufacturer_Part_Number: 19-217/BHC-ZL1M2RY/6T; Full_Alternate_Internal_Part_Number: MCD-01131; Component_Country_Of_Origin: China; ShowFields: YES; ID: 4898
R3 R11-R13 = Res_1K_1%_0402: as R303 on sheet MPU_18x18
R4 = Res_330_1%_0402: Resistor,330R,0402,1%,YAGEO; Manuf_Part_1: RC0402FR-07330RL; Fitted: YES; Ordered_By: Subcon
R5 R6 = Res_680R_1%_0402: Resistor,680R,0402,1%,1/16W; Manuf_Part_1: RC0402FR-07680RL; Manuf_1: YAGEO; Ordered_By: Subcon; Fitted: YES
R8 = Res_10K_1%_0402: Resistor,10K,0402,1%,YAGEO; Manuf_Part_1: RC0402FR-0710KL; Ordered_By: subcon
R9 R10 = Res_100_1%_0402: Resistor,100R,0402,1%,YAGEO; Manuf_Part_1: RC0402FR-07100RL; Order_Code: 9239111; Fitted: YES; Ordered_By: Subcon
R16-R25 = Res_0_5%_0402: as R28 on sheet MPU_18x18
SB5-SB7 = SB_ON: as SB1 on sheet MPU_18x18
SW1 = SWITCH_4WAY: Quad SPST surface mount switch. 1.27mm pitch. Tinned legs.; Part_Type: SWITCH; Manuf_1: CTS; Fitted: YES; Ordered_By: Subcon
TP1 = TP 1mm: Test Point; Fitted: YES
U2 = ESDALC6V1-1U2: ESD protection 6V1; Part_Type: Diode; Manuf_1: STMICROELECTRONICS; ECCN_US: EAR99; ECCN_EU: NEC; Ordered_By: Subcon; Fitted: YES

## Sheet ST_LINK_V2-1.SCHDOC: ST-LINK/V2-1
size A4; DocumentNumber: MB1263; Revision: C-04; SheetNumber: 10; SheetTotal: 11; Project: STM32MP157-EVAL
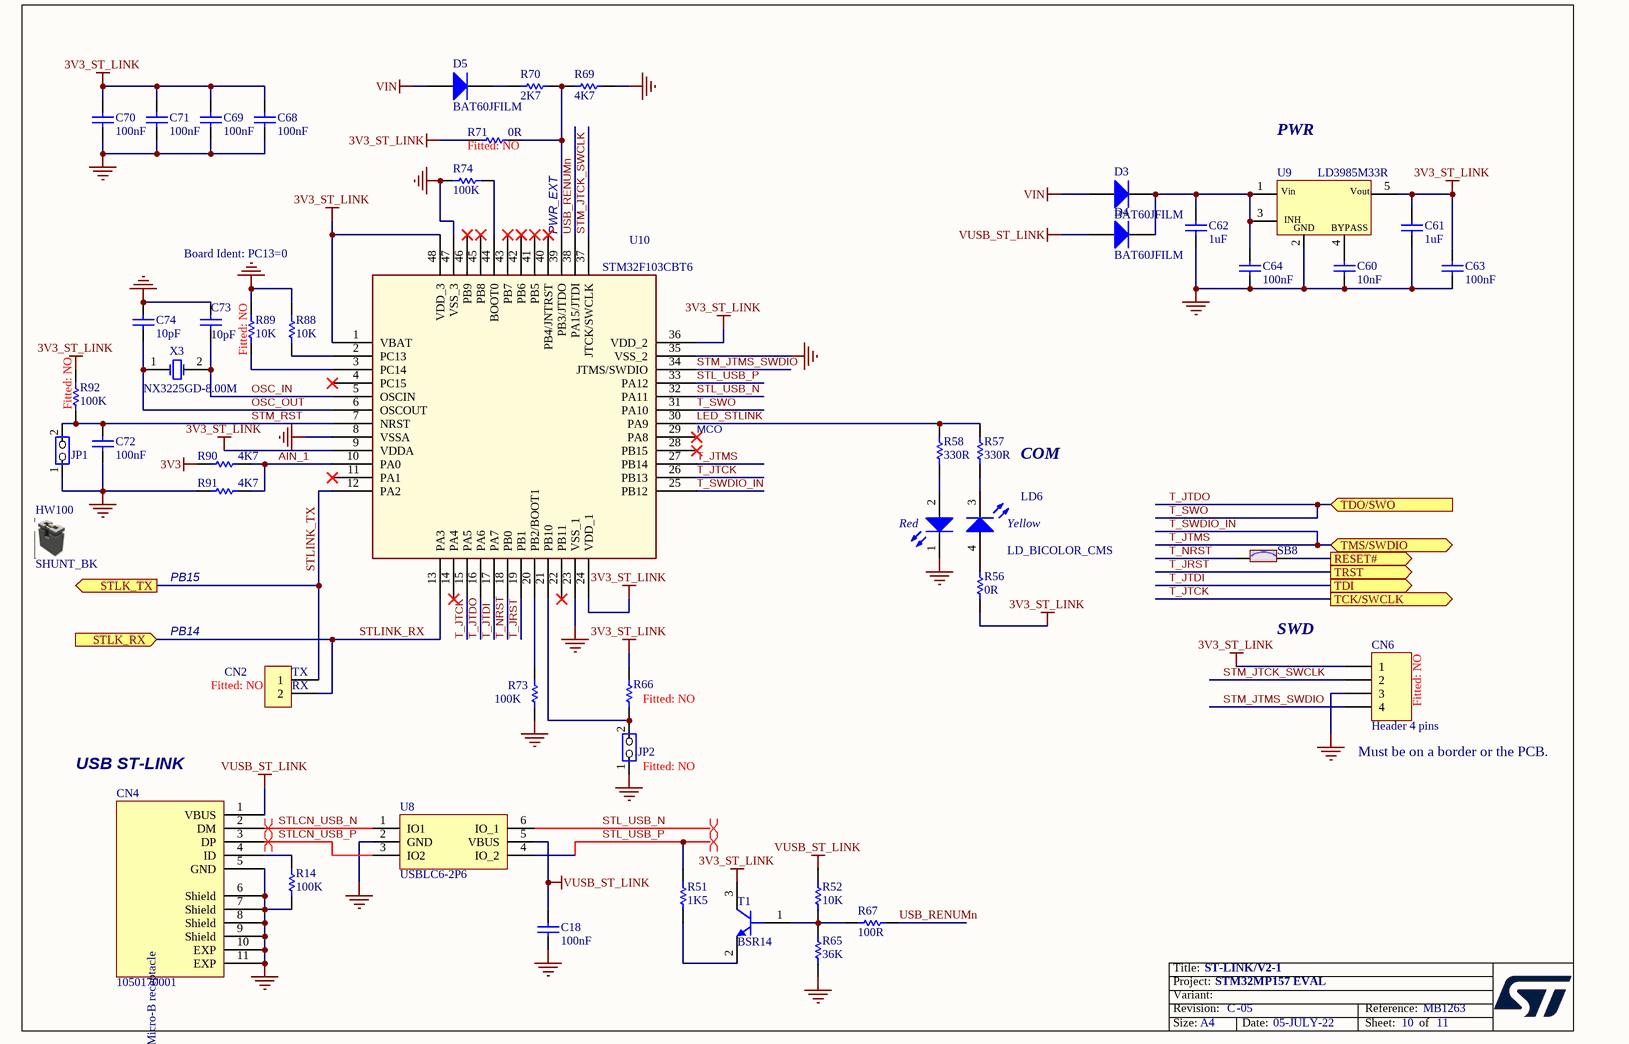
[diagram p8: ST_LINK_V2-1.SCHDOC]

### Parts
C18  100nF  [C0402]
C60  10nF  [C0603]
C61  1uF  [C0603]
C62  1uF  [C0603]
C63  100nF  [C0402]
C64  100nF  [C0402]
C68  100nF  [C0402]
C69  100nF  [C0402]
C70  100nF  [C0402]
C71  100nF  [C0402]
C72  100nF  [C0402]
C73  10pF  [C0402]
C74  10pF  [C0402]
CN2  Fitted: NO  [CON_SAMTEC_TSW-102-07-G-S]  (hidden comment: header 2 pins 2.54mm)
CN4  1050170001  [CON_USBMICROB_MOLEX_105017-0001_H2P90]
CN6  Header 4 pins  Fitted: NO  [CON_SAMTEC_TSW-104-07-G-S]
D3  BAT60JFILM  [DIO_SOD323]
D4  BAT60JFILM  [DIO_SOD323]
D5  BAT60JFILM  [DIO_SOD323]
HW100  SHUNT_BK  (mechanical)
JP1  Jumper_2.54mm  [CON_SAMTEC_TSW-102-07-G-S]  (value not drawn)
JP2  Fitted: NO  [CON_SAMTEC_TSW-102-07-G-S]  (hidden comment: Jumper_2.54mm)
LD6  LD_BICOLOR_CMS  [LED_BI-GR_HSMF-A201-A00J1]
R14  100K  [R0402]
R51  1K5  [R0402]
R52  10K  [R0402]
R56  0R  [R0402]
R57  330R  [R0402]
R58  330R  [R0402]
R65  36K  [R0402]
R66  Fitted: NO  [R0402]  (hidden comment: 1K)
R67  100R  [R0402]
R69  4K7  [R0402]
R70  2K7  [R0402]
R71  0R  Fitted: NO  [R0402]
R73  100K  [R0402]
R74  100K  [R0402]
R88  10K  [R0402]
R89  10K  Fitted: NO  [R0402]
R90  4K7  [R0402]
R91  4K7  [R0402]
R92  100K  Fitted: NO  [R0402]
SB8  SB_ON  [SOLDER-BRIDGE_R0603-0R]  (value not drawn)
T1  BSR14  [NPN_SOT23]
U8  USBLC6-2P6  [ESD_SOT666]
U9  LD3985M33R  [REG_SOT23-5L]
U10  STM32F103CBT6  [ICC_LQFP48_7X7_P050]
X3  NX3225GD-8.00M  [CRY_NX3225GD_2P]

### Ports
RESET# (out), STLK_RX (in), STLK_TX (out), TCK/SWCLK (out), TDI (out), TDO/SWO (in), TMS/SWDIO (bidir), TRST (out)

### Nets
3V3: R90.1
3V3_ST_LINK: C61.1 C63.2 C68.2 C69.2 C70.2 C71.2 CN6.1 R56.1 R66.1 R71.1 R92.2 T1.3(C) U9.5(Vout) U10.1(VBAT) U10.9(VDDA) U10.24(VDD_1) U10.36(VDD_2) U10.48(VDD_3)
GND: C18.1 C60.1 C61.2 C62.2 C63.1 C64.1 C68.1 C69.1 C70.1 C71.1 C72.2 C73.2 C74.2 CN4.5(GND) CN4.6(Shield) CN4.7(Shield) CN4.8(Shield) CN4.9(Shield) CN4.10(EXP) CN4.11(EXP) CN6.3 JP1.1(COMMON) JP2.1(COMMON) LD6.1(RED_cathode) R14.1 R65.2 R69.2 R73.1 R74.2 R88.2 R89.2 R91.1 U8.2(GND) U9.2(GND) U10.8(VSSA) U10.23(VSS_1) U10.35(VSS_2) U10.47(VSS_3)
VIN: D3.1(A) D5.1(A)
VUSB_ST_LINK: C18.2 CN4.1(VBUS) D4.1(A) R52.2 U8.5(VBUS)
AIN_1: R90.2 R91.2 U10.10(PA0)
LED_STLINK: R57.2 R58.2 U10.30(PA9)
OSC_IN: C73.1 U10.5(OSCIN) X3.2(OSC2)
OSC_OUT: C74.1 U10.6(OSCOUT) X3.1(OSC1)
RESET#: SB8.2 ; port RESET#
STL_USB_N: U8.6(IO_1) U10.32(PA11)
STL_USB_P: R51.1 U8.4(IO_2) U10.33(PA12)
STLCN_USB_N: CN4.2(DM) U8.1(IO1)
STLCN_USB_P: CN4.3(DP) U8.3(IO2)
STLINK_RX: CN2.2 U10.13(PA3) ; port STLK_RX
STLINK_TX: CN2.1 U10.12(PA2) ; port STLK_TX
STM_JTCK_SWCLK: CN6.2 U10.37(JTCK/SWCLK)
STM_JTMS_SWDIO: CN6.4 U10.34(JTMS/SWDIO)
STM_RST: C72.1 JP1.2(NO) R92.1 U10.7(NRST)
T_JRST: U10.19(PB1) ; port TRST
T_JTCK: U10.15(PA5) U10.26(PB13) ; port TCK/SWCLK
T_JTDI: U10.17(PA7) ; port TDI
T_JTDO: U10.16(PA6) U10.31(PA10) ; port TDO/SWO  [also labelled T_SWO]
T_JTMS: U10.25(PB12) U10.27(PB14) ; port TMS/SWDIO  [also labelled T_SWDIO_IN]
T_NRST: SB8.1 U10.18(PB0)
USB_RENUMn: R67.2 U10.38(PA15/JTDI)
NetC60_2: C60.2 U9.4(BYPASS)
NetC62_1: C62.1 C64.2 D3.2(K) D4.2(K) U9.1(Vin) U9.3(CE)
NetCN4_4: CN4.4(ID) R14.2
NetD5_2: D5.2(K) R70.1
NetJP2_2: JP2.2(NO) R66.2 U10.21(PB10)
NetLD6_2: LD6.2(Red_anode) R58.1
NetLD6_3: LD6.3(YellowGreen_cathode) R57.1
NetLD6_4: LD6.4(YellowGreen_anode) R56.2
NetR51_2: R51.2 T1.2(E)
NetR52_1: R52.1 R65.1 R67.1 T1.1(B)
NetR69_1: R69.1 R70.2 R71.2 U10.39(PB3/JTDO)
NetR73_2: R73.2 U10.20(PB2/BOOT1)
NetR74_1: R74.1 U10.44(BOOT0)
NetR88_1: R88.1 U10.2(PC13)
NetR89_1: R89.1 U10.3(PC14)

Not connected (* = marked no-connect by the designer): U10 4(PC15)* 11(PA1)* 14(PA4)* 22(PB11)* 28(PB15)* 29(PA8)* 40(PB4/JNTRST)* 41(PB5)* 42(PB6)* 43(PB7)* 45(PB8)* 46(PB9)*

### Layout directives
differential pair: (no net found under the mark), STL_USB_N, STL_USB_P

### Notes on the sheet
- PWR
- (near U10) PWR_EXT
- Board Ident: PC13=0
- (near U10) MCO
- (near R57) COM
- PB15
- PB14
- SWD
- (near CN2) TX
- (near CN2) RX
- USB ST-LINK
- (near CN6) Must be on a border or the PCB.

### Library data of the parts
C18 C63 C64 C68-C72 = Cap_100nF_X7R_10%_0402: as C38 on sheet MPU_18x18
C60 = Cap_10nF_X7R_10%_0603: Capacitor,10nF,50V,X7R,10%,0603,YAGEO; Manuf_Part_1: CC0603KRX7R9BB103; Fitted: YES; Ordered_By: Subcon
C61 C62 = Cap_1uF_X5R_10%_0603: as C55 on sheet SD3 card
C73 C74 = Cap_10pF_NPO_5%_0402: Capacitor,10pF,50V,NPO,5%,0402,YAGEO; Order_Code: CC0402JRNPO9BN100; Fitted: YES; Ordered_By: subcon
CN2 = Header 2 pins: Manuf_1: SAMTEC; Manuf_Part_2: 4711955140470; Manuf_2: KONTEC; Manuf_Part_1: TSW-102-07-x-S; Order_Code: 423-2841; Ordered_By: Subcon
CN4 = 1050170001: USB-MICRO-B, 1050170001, SMT, MOLEX; Fitted: YES; Ordered_By: Subcon
CN6 = Header 4: Header, 4-Pin; Manuf_1: Samtec; Manuf_Part_1: TSW-104-07-x-S; Ordered_By: Subcon
D3-D5 = BAT60JFILM: Manuf_1: STM; Ordered_By: Subcon; ECCN_US/EU: EAR99/NEC; Ref St: 9151097; Fitted: YES
HW100 = Shunt 2.54mm: SHUNT 2.54mm BLACK; Manuf_1: SAMTEC; Manuf_Part_1: SNT-100-BK-G; Fitted: YES; Ordered_By: Subcon
JP1 = TSW-102-07-x-S: as JP6 on sheet Peripherals
JP2 = TSW-102-07-x-S: Connector jumper 1 position; Manuf_1: SAMTEC; Manuf_Part_2: 4711955140470; Manuf_2: KONTEC; Order_Code: 423-2841; Ordered_By: Subcon
LD6 = LD_BICOLOR_CMS: Bicolor Led; Manuf_Part_1: HSMF-A201-A00J1; Manuf_1: Avago Technologies; Manuf_2: everluck; Manuf_Part_2: LE-RGW35280; Ordered_By: Subcon; ECCN_US/EU: EAR99/NEC; Fitted: YES
R14 R73 R74 = Res_100K_1%_0402: Resistor,100K,0402,1%,YAGEO; Manuf_Part_2: RT0402FRE07100KL; Manuf_Part_1: RC0402FR-07100KL; Fitted: YES; Ordered_By: Subcon
R51 = Res_1K5_1%_0402: as R30 on sheet MPU_18x18
R52 R88 = Res_10K_1%_0402: as R37 on sheet SD3 card
R56 = Res_0_5%_0402: as R28 on sheet MPU_18x18
R57 R58 = Res_330_1%_0402: as R4 on sheet Peripherals
R65 = Res_36K_1%_0402: Resistor,36K,0402,1%,YAGEO; Manuf_Part_1: RC0402FR-0736KL; Fitted: YES; Ordered_By: Subcon
R66 = Res_1K_1%_0402: Resistor,1K,0402,1%,YAGEO; Manuf_Part_1: RC0402FR-071KL; Ordered_By: Subcon
R67 = Res_100_1%_0402: as R9 on sheet Peripherals
R69 R90 R91 = Res_4K7_1%_0402: Resistor,4K7,0402,1%,YAGEO; Manuf_Part_2: RT0402FRE074K7L; Manuf_Part_1: RC0402FR-074K7L; Fitted: YES; Ordered_By: Subcon
R70 = Res_2K7_1%_0402: Resistor,2K7,0402,1%,YAGEO; Manuf_Part_1: RC0402FR-072K7L; Fitted: YES; Ordered_By: Subcon
R71 = Res_0_5%_0402: as R26 on sheet MPU_18x18
R89 = Res_10K_1%_0402: as R38 on sheet SD3 card
R92 = Res_100K_1%_0402: Resistor,100K,0402,1%,YAGEO; Manuf_Part_2: RT0402FRE07100KL; Manuf_Part_1: RC0402FR-07100KL; Ordered_By: Subcon
SB8 = SB_ON: as SB1 on sheet MPU_18x18
T1 = 9013-SOT23_1: NPN Bipolar Transistor; Manuf_1: NXP; Order_Code: 1081310; ECCN_US/EU: EAR99/NEC; Fitted: YES; Ordered_By: Subcon
U8 = USBLC6-2P6: USB ESD protection; Manuf_1: STM; Ordered_By: Subcon; ECCN_US/EU: EAR99/NEC; Fitted: YES
U9 = LD3985M33R: Ultra low drop-low noise BiCMOS voltage, regulators low ESR capacitors compatible; Manuf_1: STM; Ordered_By: Subcon; Ref St: 9176161; ECCN_US/EU: EAR99/NEC; Fitted: YES
U10 = STM32F103CBT6: Medium-density performance line ARM-based 32-bit MCU with 128KB Flash; Manuf_1: STM; Ordered_By: Subcon; ECCN_US/EU: 3A991A2/NEC; Fitted: YES
X3 = XTAL_8M_NX3225GD: Crystal 8Mhz, 8pF, -+50PPM, SMD; Manuf_1: NDK; Order_Code: NX3225GD 8MHz EXS00A-CG04874; ECCN_US/EU: EAR99/NEC; NDK Ref: X3127326; Ref St: 9157029; Ordered_By: Subcon; Fitted: YES

## Sheet Samtec Connectors QTH_North_South.SchDoc: Samtec Connectors
size A3; Date: 01-DEC-2013; CompanyName: STMicroelectronics; Organization: Microcontrollers Division; Address1: 12, Rue Jules HOROWITZ; Address2: 38019 Grenoble; Address3: FRANCE; DocumentNumber: MB1263; Revision: C-04; SheetNumber: 6; SheetTotal: 11; Project: STM32MP157-EVAL; PageSetup: Record=PageOptions¦CenterHorizontal=True¦CenterVertical=True¦PrintScale=1.00¦XCorrection=1.00¦YCorrection=1.00¦PrintKind=1¦BorderSize=5000000¦LeftOffset=0¦BottomOffset=0¦Orientation=2¦PaperLength=1000¦PaperWidth=1000¦Scale=100¦PaperSource=7¦PrintQuality=-3¦MediaType=1¦DitherType=10¦PrintScaleMode=1¦PaperKind=A3¦PaperIndex=8
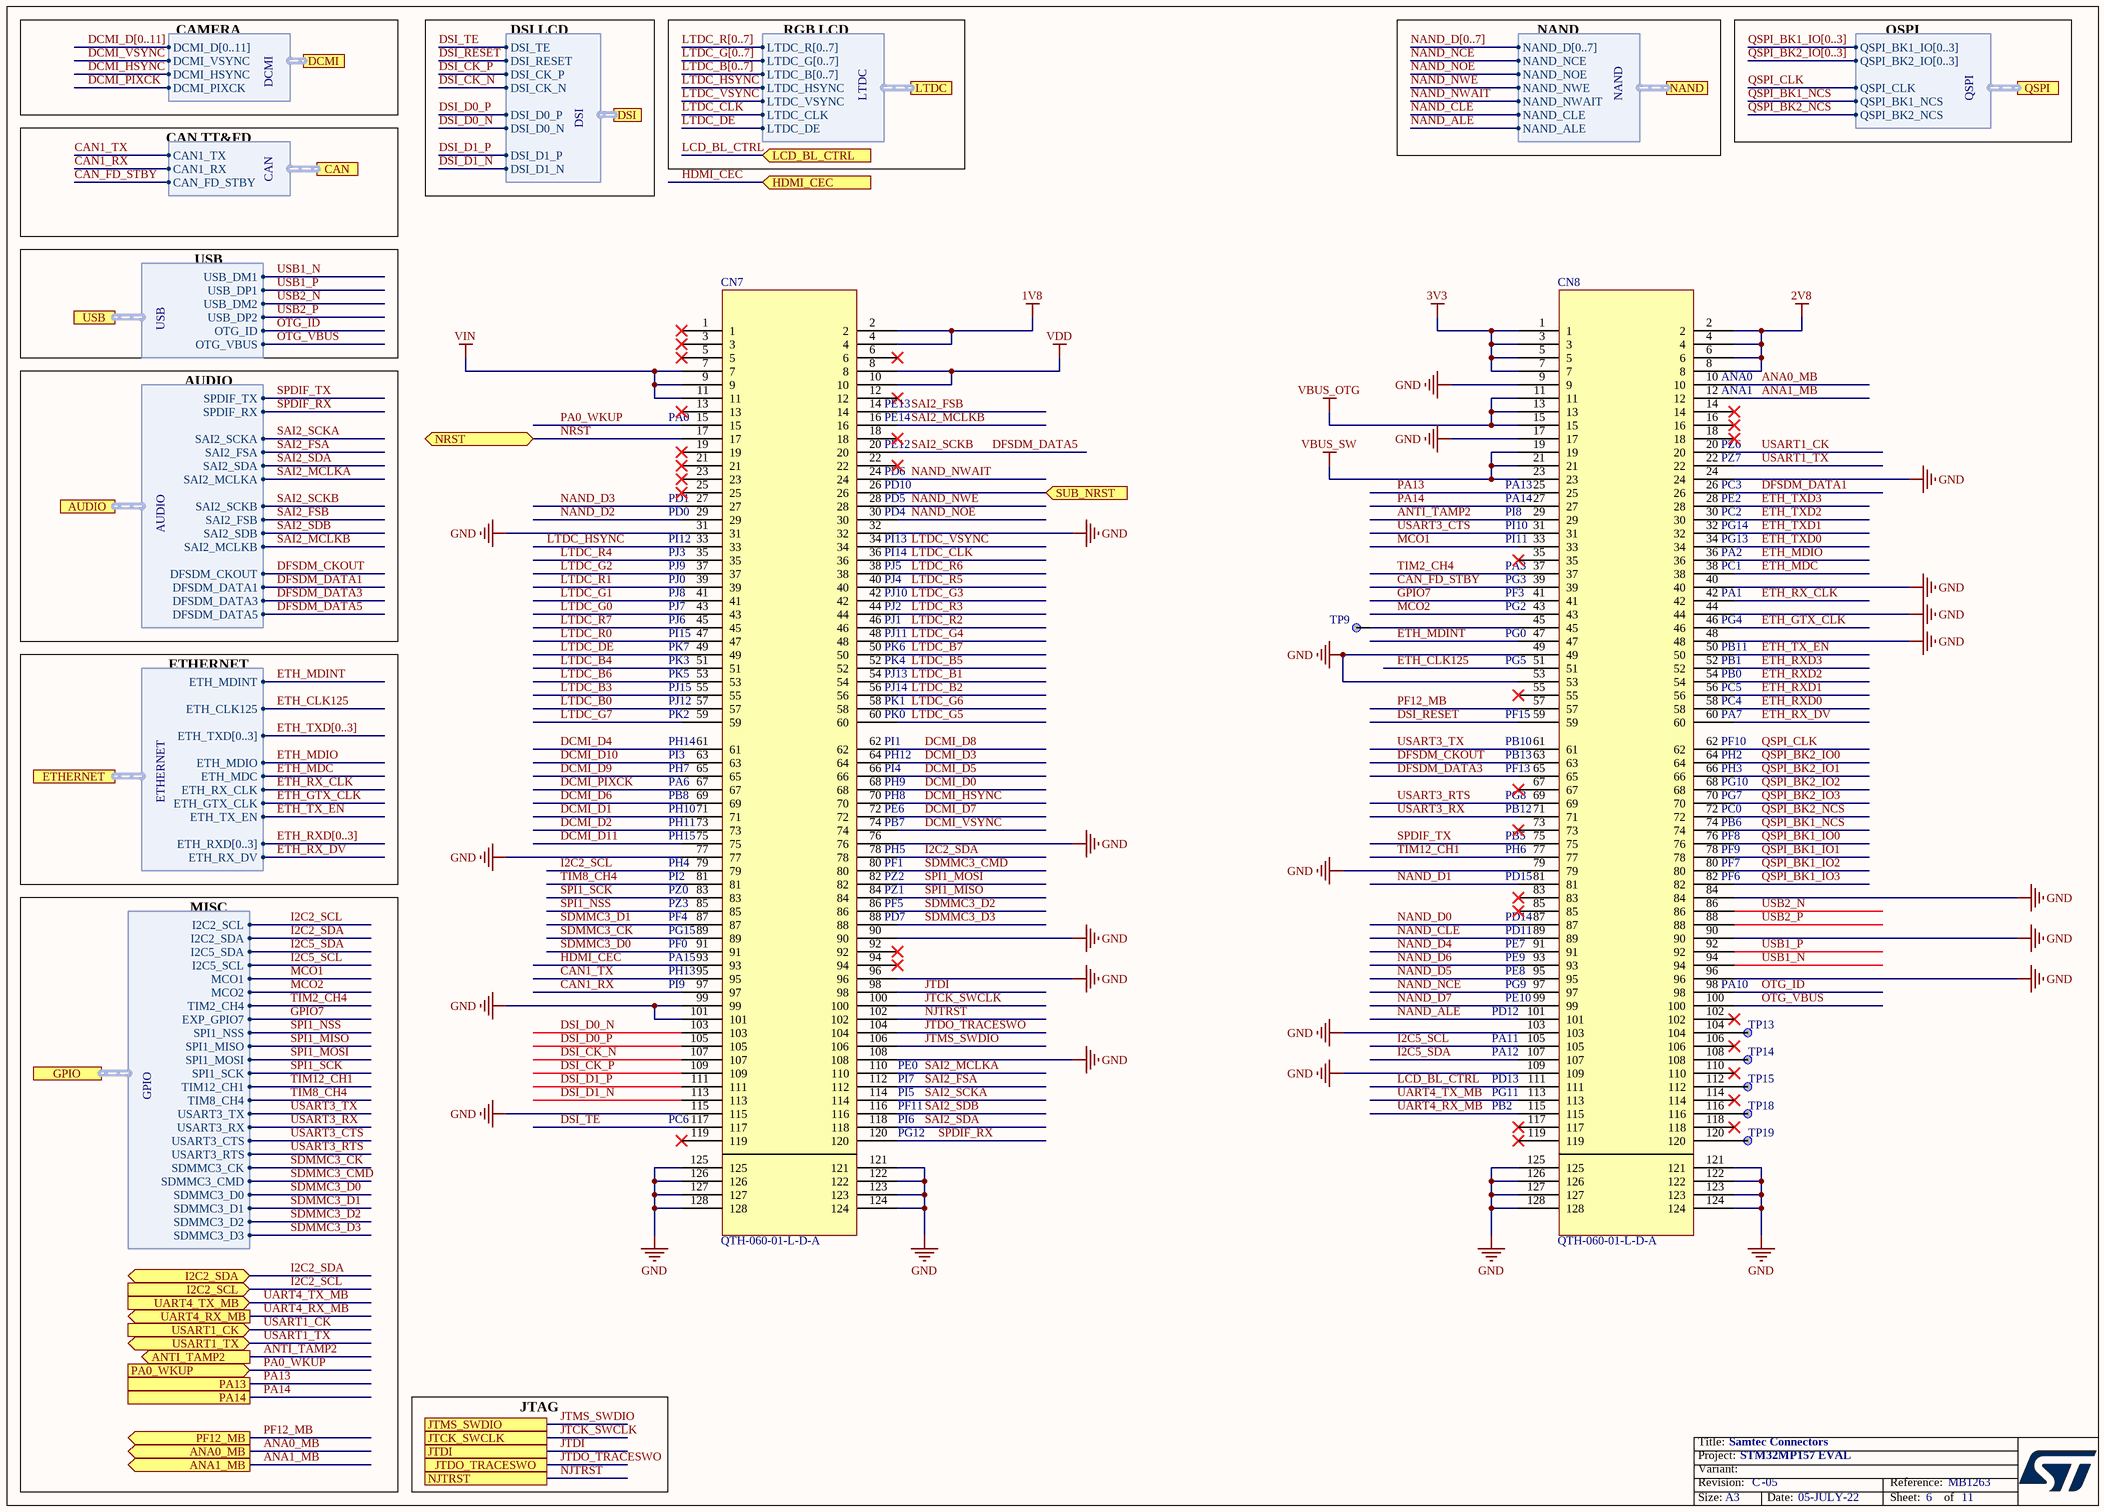
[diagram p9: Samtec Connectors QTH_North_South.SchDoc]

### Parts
CN7  QTH-060-01-L-D-A  [CON_SAMTEC_QTH-060-01-L-D-A]
CN8  QTH-060-01-L-D-A  [CON_SAMTEC_QTH-060-01-L-D-A]
TP9  TP  [TP_SMD_1MM]  (value not drawn)  (no BOM)
TP13  TP  [TP_SMD_1MM]  (value not drawn)  (no BOM)
TP14  TP  [TP_SMD_1MM]  (value not drawn)  (no BOM)
TP15  TP  [TP_SMD_1MM]  (value not drawn)  (no BOM)
TP18  TP  [TP_SMD_1MM]  (value not drawn)  (no BOM)
TP19  TP  [TP_SMD_1MM]  (value not drawn)  (no BOM)

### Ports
ANA0_MB (out), ANA1_MB (out), ANTI_TAMP2 (out), AUDIO (harness AUDIO), CAN (harness CAN), DCMI (harness DCMI), DSI (harness DSI), ETHERNET (harness ETHERNET), GPIO (harness GPIO), HDMI_CEC (in), I2C2_SCL (in), I2C2_SDA (bidir), JTCK_SWCLK, JTDI, JTDO_TRACESWO, JTMS_SWDIO, LCD_BL_CTRL (in), LTDC (harness LTDC), NAND (harness NAND), NJTRST, NRST (bidir), PA0_WKUP (in), PA13, PA14, PF12_MB (out), QSPI (harness QSPI), SUB_NRST (in), UART4_RX_MB (out), UART4_TX_MB (in), USART1_CK (in), USART1_TX (bidir), USB (harness USB)

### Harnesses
NAND: NAND_D[0..7], NAND_NCE, NAND_NOE, NAND_NWE, NAND_NWAIT, NAND_CLE, NAND_ALE
QSPI: QSPI_BK1_IO[0..3], QSPI_BK2_IO[0..3], QSPI_CLK, QSPI_BK1_NCS, QSPI_BK2_NCS
DSI: DSI_CK_P, DSI_CK_N, DSI_D0_P, DSI_D0_N, DSI_D1_P, DSI_D1_N, DSI_TE, DSI_RESET
LTDC: LTDC_R[0..7], LTDC_G[0..7], LTDC_B[0..7], LTDC_HSYNC, LTDC_VSYNC, LTDC_CLK, LTDC_DE
ETHERNET: ETH_MDINT, ETH_CLK125, ETH_TXD[0..3], ETH_MDIO, ETH_MDC, ETH_RX_CLK, ETH_GTX_CLK, ETH_TX_EN, ETH_RXD[0..3], ETH_RX_DV
USB: USB_DM1, USB_DP1, USB_DM2, USB_DP2, OTG_ID, OTG_VBUS
DCMI: DCMI_D[0..11], DCMI_VSYNC, DCMI_HSYNC, DCMI_PIXCK
CAN: CAN1_TX, CAN1_RX, CAN_FD_STBY
GPIO: I2C2_SCL, I2C2_SDA, I2C5_SDA, MCO1, MCO2, TIM2_CH4, EXP_GPIO7, SPI1_NSS, SPI1_MISO, SPI1_MOSI, SPI1_SCK, TIM12_CH1, TIM8_CH4, USART3_TX, USART3_RX, USART3_CTS, USART3_RTS, SDMMC3_CK, SDMMC3_CMD, SDMMC3_D0, SDMMC3_D1, SDMMC3_D2, SDMMC3_D3, I2C5_SCL
AUDIO: SPDIF_TX, SPDIF_RX, SAI2_SCKA, SAI2_FSA, SAI2_SDA, SAI2_SDB, SAI2_MCLKA, DFSDM_CKOUT, DFSDM_DATA1, DFSDM_DATA3, DFSDM_DATA5, SAI2_SCKB, SAI2_FSB, SAI2_MCLKB

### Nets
1V8: CN7.2 CN7.4
2V8: CN8.2 CN8.4 CN8.6 CN8.8
3V3: CN8.1 CN8.3 CN8.5 CN8.7
GND: CN7.31 CN7.32 CN7.76 CN7.77 CN7.90 CN7.96 CN7.99 CN7.101 CN7.108 CN7.115 CN7.121 CN7.122 CN7.123 CN7.124 CN7.125 CN7.126 CN7.127 CN7.128 CN8.9 CN8.17 CN8.24 CN8.40 CN8.44 CN8.48 CN8.49 CN8.53 CN8.79 CN8.84 CN8.90 CN8.96 CN8.103 CN8.109 CN8.121 CN8.122 CN8.123 CN8.124 CN8.125 CN8.126 CN8.127 CN8.128
VBUS_OTG: CN8.11 CN8.13 CN8.15
VBUS_SW: CN8.19 CN8.21 CN8.23
VDD: CN7.8 CN7.10
VIN: CN7.7 CN7.9 CN7.11
ANA0_MB: CN8.10 ; port ANA0_MB
ANA1_MB: CN8.12 ; port ANA1_MB
ANTI_TAMP2: CN8.29 ; port ANTI_TAMP2
CAN1_RX: CN7.97 ; port CAN.CAN1_RX
CAN1_TX: CN7.95 ; port CAN.CAN1_TX
CAN_FD_STBY: CN8.39 ; port CAN.CAN_FD_STBY
DCMI_D0: CN7.68
DCMI_D1: CN7.71
DCMI_D2: CN7.73
DCMI_D3: CN7.64
DCMI_D4: CN7.61
DCMI_D5: CN7.66
DCMI_D6: CN7.69
DCMI_D7: CN7.72
DCMI_D8: CN7.62
DCMI_D9: CN7.65
DCMI_D10: CN7.63
DCMI_D11: CN7.75
DCMI_HSYNC: CN7.70 ; port DCMI.DCMI_HSYNC
DCMI_PIXCK: CN7.67 ; port DCMI.DCMI_PIXCK
DCMI_VSYNC: CN7.74 ; port DCMI.DCMI_VSYNC
DFSDM_CKOUT: CN8.63 ; port AUDIO.DFSDM_CKOUT
DFSDM_DATA1: CN8.26 ; port AUDIO.DFSDM_DATA1
DFSDM_DATA3: CN8.65 ; port AUDIO.DFSDM_DATA3
DFSDM_DATA5: CN7.20 ; port AUDIO.DFSDM_DATA5, port AUDIO.SAI2_SCKB  [also labelled SAI2_SCKB]
DSI_CK_N: CN7.107 ; port DSI.DSI_CK_N
DSI_CK_P: CN7.109 ; port DSI.DSI_CK_P
DSI_D0_N: CN7.103 ; port DSI.DSI_D0_N
DSI_D0_P: CN7.105 ; port DSI.DSI_D0_P
DSI_D1_N: CN7.113 ; port DSI.DSI_D1_N
DSI_D1_P: CN7.111 ; port DSI.DSI_D1_P
DSI_RESET: CN8.59 ; port DSI.DSI_RESET
DSI_TE: CN7.117 ; port DSI.DSI_TE
ETH_CLK125: CN8.51 ; port ETHERNET.ETH_CLK125
ETH_GTX_CLK: CN8.46 ; port ETHERNET.ETH_GTX_CLK
ETH_MDC: CN8.38 ; port ETHERNET.ETH_MDC
ETH_MDINT: CN8.47 ; port ETHERNET.ETH_MDINT
ETH_MDIO: CN8.36 ; port ETHERNET.ETH_MDIO
ETH_RX_CLK: CN8.42 ; port ETHERNET.ETH_RX_CLK
ETH_RX_DV: CN8.60 ; port ETHERNET.ETH_RX_DV
ETH_RXD0: CN8.58
ETH_RXD1: CN8.56
ETH_RXD2: CN8.54
ETH_RXD3: CN8.52
ETH_TX_EN: CN8.50 ; port ETHERNET.ETH_TX_EN
ETH_TXD0: CN8.34
ETH_TXD1: CN8.32
ETH_TXD2: CN8.30
ETH_TXD3: CN8.28
GPIO7: CN8.41 ; port GPIO.EXP_GPIO7
HDMI_CEC: CN7.93 ; port HDMI_CEC
I2C2_SCL: CN7.79 ; port I2C2_SCL, port GPIO.I2C2_SCL
I2C2_SDA: CN7.78 ; port I2C2_SDA, port GPIO.I2C2_SDA
I2C5_SCL: CN8.105 ; port GPIO.I2C5_SCL
I2C5_SDA: CN8.107 ; port GPIO.I2C5_SDA
JTCK_SWCLK: CN7.100 ; port JTCK_SWCLK
JTDI: CN7.98 ; port JTDI
JTDO_TRACESWO: CN7.104 ; port JTDO_TRACESWO
JTMS_SWDIO: CN7.106 ; port JTMS_SWDIO
LCD_BL_CTRL: CN8.111 ; port LCD_BL_CTRL
LTDC_B0: CN7.57
LTDC_B1: CN7.54
LTDC_B2: CN7.56
LTDC_B3: CN7.55
LTDC_B4: CN7.51
LTDC_B5: CN7.52
LTDC_B6: CN7.53
LTDC_B7: CN7.50
LTDC_CLK: CN7.36 ; port LTDC.LTDC_CLK
LTDC_DE: CN7.49 ; port LTDC.LTDC_DE
LTDC_G0: CN7.43
LTDC_G1: CN7.41
LTDC_G2: CN7.37
LTDC_G3: CN7.42
LTDC_G4: CN7.48
LTDC_G5: CN7.60
LTDC_G6: CN7.58
LTDC_G7: CN7.59
LTDC_HSYNC: CN7.33 ; port LTDC.LTDC_HSYNC
LTDC_R0: CN7.47
LTDC_R1: CN7.39
LTDC_R2: CN7.46
LTDC_R3: CN7.44
LTDC_R4: CN7.35
LTDC_R5: CN7.40
LTDC_R6: CN7.38
LTDC_R7: CN7.45
LTDC_VSYNC: CN7.34 ; port LTDC.LTDC_VSYNC
MCO1: CN8.33 ; port GPIO.MCO1
MCO2: CN8.43 ; port GPIO.MCO2
NAND_ALE: CN8.101 ; port NAND.NAND_ALE
NAND_CLE: CN8.89 ; port NAND.NAND_CLE
NAND_D0: CN8.87
NAND_D1: CN8.81
NAND_D2: CN7.29
NAND_D3: CN7.27
NAND_D4: CN8.91
NAND_D5: CN8.95
NAND_D6: CN8.93
NAND_D7: CN8.99
NAND_NCE: CN8.97 ; port NAND.NAND_NCE
NAND_NOE: CN7.30 ; port NAND.NAND_NOE
NAND_NWAIT: CN7.24 ; port NAND.NAND_NWAIT
NAND_NWE: CN7.28 ; port NAND.NAND_NWE
NJTRST: CN7.102 ; port NJTRST
NRST: CN7.17 ; port NRST
OTG_ID: CN8.98 ; port USB.OTG_ID
OTG_VBUS: CN8.100 ; port USB.OTG_VBUS
PA0_WKUP: CN7.15 ; port PA0_WKUP
PA13: CN8.25 ; port PA13
PA14: CN8.27 ; port PA14
PF12_MB: CN8.57 ; port PF12_MB
QSPI_BK1_IO0: CN8.76
QSPI_BK1_IO1: CN8.78
QSPI_BK1_IO2: CN8.80
QSPI_BK1_IO3: CN8.82
QSPI_BK1_NCS: CN8.74 ; port QSPI.QSPI_BK1_NCS
QSPI_BK2_IO0: CN8.64
QSPI_BK2_IO1: CN8.66
QSPI_BK2_IO2: CN8.68
QSPI_BK2_IO3: CN8.70
QSPI_BK2_NCS: CN8.72 ; port QSPI.QSPI_BK2_NCS
QSPI_CLK: CN8.62 ; port QSPI.QSPI_CLK
SAI2_FSA: CN7.112 ; port AUDIO.SAI2_FSA
SAI2_FSB: CN7.14 ; port AUDIO.SAI2_FSB
SAI2_MCLKA: CN7.110 ; port AUDIO.SAI2_MCLKA
SAI2_MCLKB: CN7.16 ; port AUDIO.SAI2_MCLKB
SAI2_SCKA: CN7.114 ; port AUDIO.SAI2_SCKA
SAI2_SDA: CN7.118 ; port AUDIO.SAI2_SDA
SAI2_SDB: CN7.116 ; port AUDIO.SAI2_SDB
SDMMC3_CK: CN7.89 ; port GPIO.SDMMC3_CK
SDMMC3_CMD: CN7.80 ; port GPIO.SDMMC3_CMD
SDMMC3_D0: CN7.91 ; port GPIO.SDMMC3_D0
SDMMC3_D1: CN7.87 ; port GPIO.SDMMC3_D1
SDMMC3_D2: CN7.86 ; port GPIO.SDMMC3_D2
SDMMC3_D3: CN7.88 ; port GPIO.SDMMC3_D3
SPDIF_RX: CN7.120 ; port AUDIO.SPDIF_RX
SPDIF_TX: CN8.75 ; port AUDIO.SPDIF_TX
SPI1_MISO: CN7.84 ; port GPIO.SPI1_MISO
SPI1_MOSI: CN7.82 ; port GPIO.SPI1_MOSI
SPI1_NSS: CN7.85 ; port GPIO.SPI1_NSS
SPI1_SCK: CN7.83 ; port GPIO.SPI1_SCK
SUB_NRST: CN7.26 ; port SUB_NRST
TIM2_CH4: CN8.37 ; port GPIO.TIM2_CH4
TIM8_CH4: CN7.81 ; port GPIO.TIM8_CH4
TIM12_CH1: CN8.77 ; port GPIO.TIM12_CH1
UART4_RX_MB: CN8.115 ; port UART4_RX_MB
UART4_TX_MB: CN8.113 ; port UART4_TX_MB
USART1_CK: CN8.20 ; port USART1_CK
USART1_TX: CN8.22 ; port USART1_TX
USART3_CTS: CN8.31 ; port GPIO.USART3_CTS
USART3_RTS: CN8.69 ; port GPIO.USART3_RTS
USART3_RX: CN8.71 ; port GPIO.USART3_RX
USART3_TX: CN8.61 ; port GPIO.USART3_TX
USB1_N: CN8.94 ; port USB.USB_DM1
USB1_P: CN8.92 ; port USB.USB_DP1
USB2_N: CN8.86 ; port USB.USB_DM2
USB2_P: CN8.88 ; port USB.USB_DP2
NetCN8_45: CN8.45 TP9.1
NetCN8_104: CN8.104 TP13.1
NetCN8_108: CN8.108 TP14.1
NetCN8_112: CN8.112 TP15.1
NetCN8_116: CN8.116 TP18.1
NetCN8_120: CN8.120 TP19.1

Not connected (* = marked no-connect by the designer): CN7 1* 3* 5* 6* 12* 13* 18* 19* 21* 22* 23* 25* 92* 94* 119*; CN8 14* 16* 18* 35* 55* 67* 73* 83* 85* 102* 106* 110* 114* 117* 118* 119*

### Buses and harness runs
bus DCMI_D[0..11]
bus ETH_RXD[0..3]
bus ETH_TXD[0..3]
bus LTDC_B[0..7]
bus LTDC_G[0..7]
bus LTDC_R[0..7]
bus NAND_D[0..7]
bus QSPI_BK1_IO[0..3]
bus QSPI_BK2_IO[0..3]

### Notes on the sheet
- CAMERA
- RGB LCD
- NAND
- QSPI
- CAN TT&FD
- DSI LCD
- USB
- (near CN8) ANA0
- (near CN7) PA0
- (near CN7) PE12
- (near CN7) PE13
- (near CN7) PE14
- (near CN8) PZ6
- (near CN8) ANA1
- (near CN7) PD1
- (near CN7) PD0
- (near CN7) PD6
- (near CN7) PD5
- (near CN7) PD4
- (near CN7) PD10
- (near CN8) PI8
- (near CN8) PA13
- (near CN8) PA14
- (near CN8) PC2
- (near CN8) PE2
- (near CN8) PZ7
- (near CN8) PC3
- (near CN7) PI12
- (near CN7) PJ3
- (near CN7) PJ9
- (near CN7) PJ0
- (near CN7) PI13
- (near CN7) PI14
- (near CN7) PJ5
- (near CN7) PJ4
- (near CN8) PI10
- (near CN8) PI11
- (near CN8) PA3
- (near CN8) PG3
- (near CN8) PC1
- (near CN8) PA2
- (near CN8) PG13
- (near CN8) PG14
- AUDIO
- (near CN7) PJ8
- (near CN7) PJ7
- (near CN7) PJ6
- (near CN7) PI15
- (near CN7) PK7
- (near CN7) PJ10
- (near CN7) PJ2
- (near CN7) PJ1
- (near CN7) PJ11
- (near CN7) PK6
- (near CN8) PF3
- (near CN8) PG2
- (near CN8) PG0
- (near CN8) PB11
- (near CN8) PA1
- (near CN8) PG4
- (near CN7) PK3
- (near CN7) PK5
- (near CN7) PJ15
- (near CN7) PJ12
- (near CN7) PK2
- (near CN7) PK4
- (near CN7) PJ13
- (near CN7) PJ14
- (near CN7) PK1
- (near CN7) PK0
- (near CN8) PG5
- (near CN8) PF15
- (near CN8) PA7
- (near CN8) PC4
- (near CN8) PC5
- (near CN8) PB0
- (near CN8) PB1
- (near CN7) PH14
- (near CN7) PI3
- (near CN7) PH7
- (near CN7) PA6
- (near CN7) PI1
- (near CN7) PH12
- (near CN7) PI4
- (near CN7) PH9
- (near CN8) PB10
- (near CN8) PB13
- (near CN8) PF13
- (near CN8) PG10
- (near CN8) PH3
- (near CN8) PH2
- (near CN8) PF10
- (near CN7) PB8
- (near CN7) PH10
- (near CN7) PH11
- (near CN7) PH15
- (near CN7) PH8
- (near CN7) PE6
- (near CN7) PB7
- (near CN7) PH5
- (near CN8) PG8
- (near CN8) PB12
- (near CN8) PB5
- (near CN8) PH6
- (near CN8) PF8
- (near CN8) PF9
- (near CN8) PB6
- (near CN8) PC0
- (near CN8) PG7
- ETHERNET
- (near CN7) PH4
- (near CN7) PI2
- (near CN7) PZ0
- (near CN7) PZ3
- (near CN7) PF4
- (near CN7) PF1
- (near CN7) PZ2
- (near CN7) PZ1
- (near CN7) PF5
- (near CN7) PD7
- (near CN8) PD15
- (near CN8) PD14
- (near CN8) PF6
- (near CN8) PF7
- (near CN7) PG15
- (near CN7) PF0
- (near CN7) PA15
- (near CN7) PH13
- (near CN7) PI9
- (near CN8) PD11
- (near CN8) PE7
- (near CN8) PE9
- (near CN8) PE8
- (near CN8) PG9
- PA10
- (near CN8) PD12
- (near CN8) PA11
- (near CN8) PA12
- (near CN8) PE10
- (near CN7) PC6
- (near CN7) PE0
- (near CN7) PI7
- (near CN7) PI5
- (near CN7) PF11
- (near CN7) PI6
- (near CN8) PD13
- (near CN8) PG11
- (near CN8) PB2
- (near CN7) PG12
- MISC
- JTAG

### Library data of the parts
CN7 CN8 = QTH-060-01-L-D-A: Samtec connector QTH 120p; Fitted: YES; Ordered_By: Subcon
TP9 TP13-TP15 TP18 TP19 = TP 1mm: Test Point; Fitted: YES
